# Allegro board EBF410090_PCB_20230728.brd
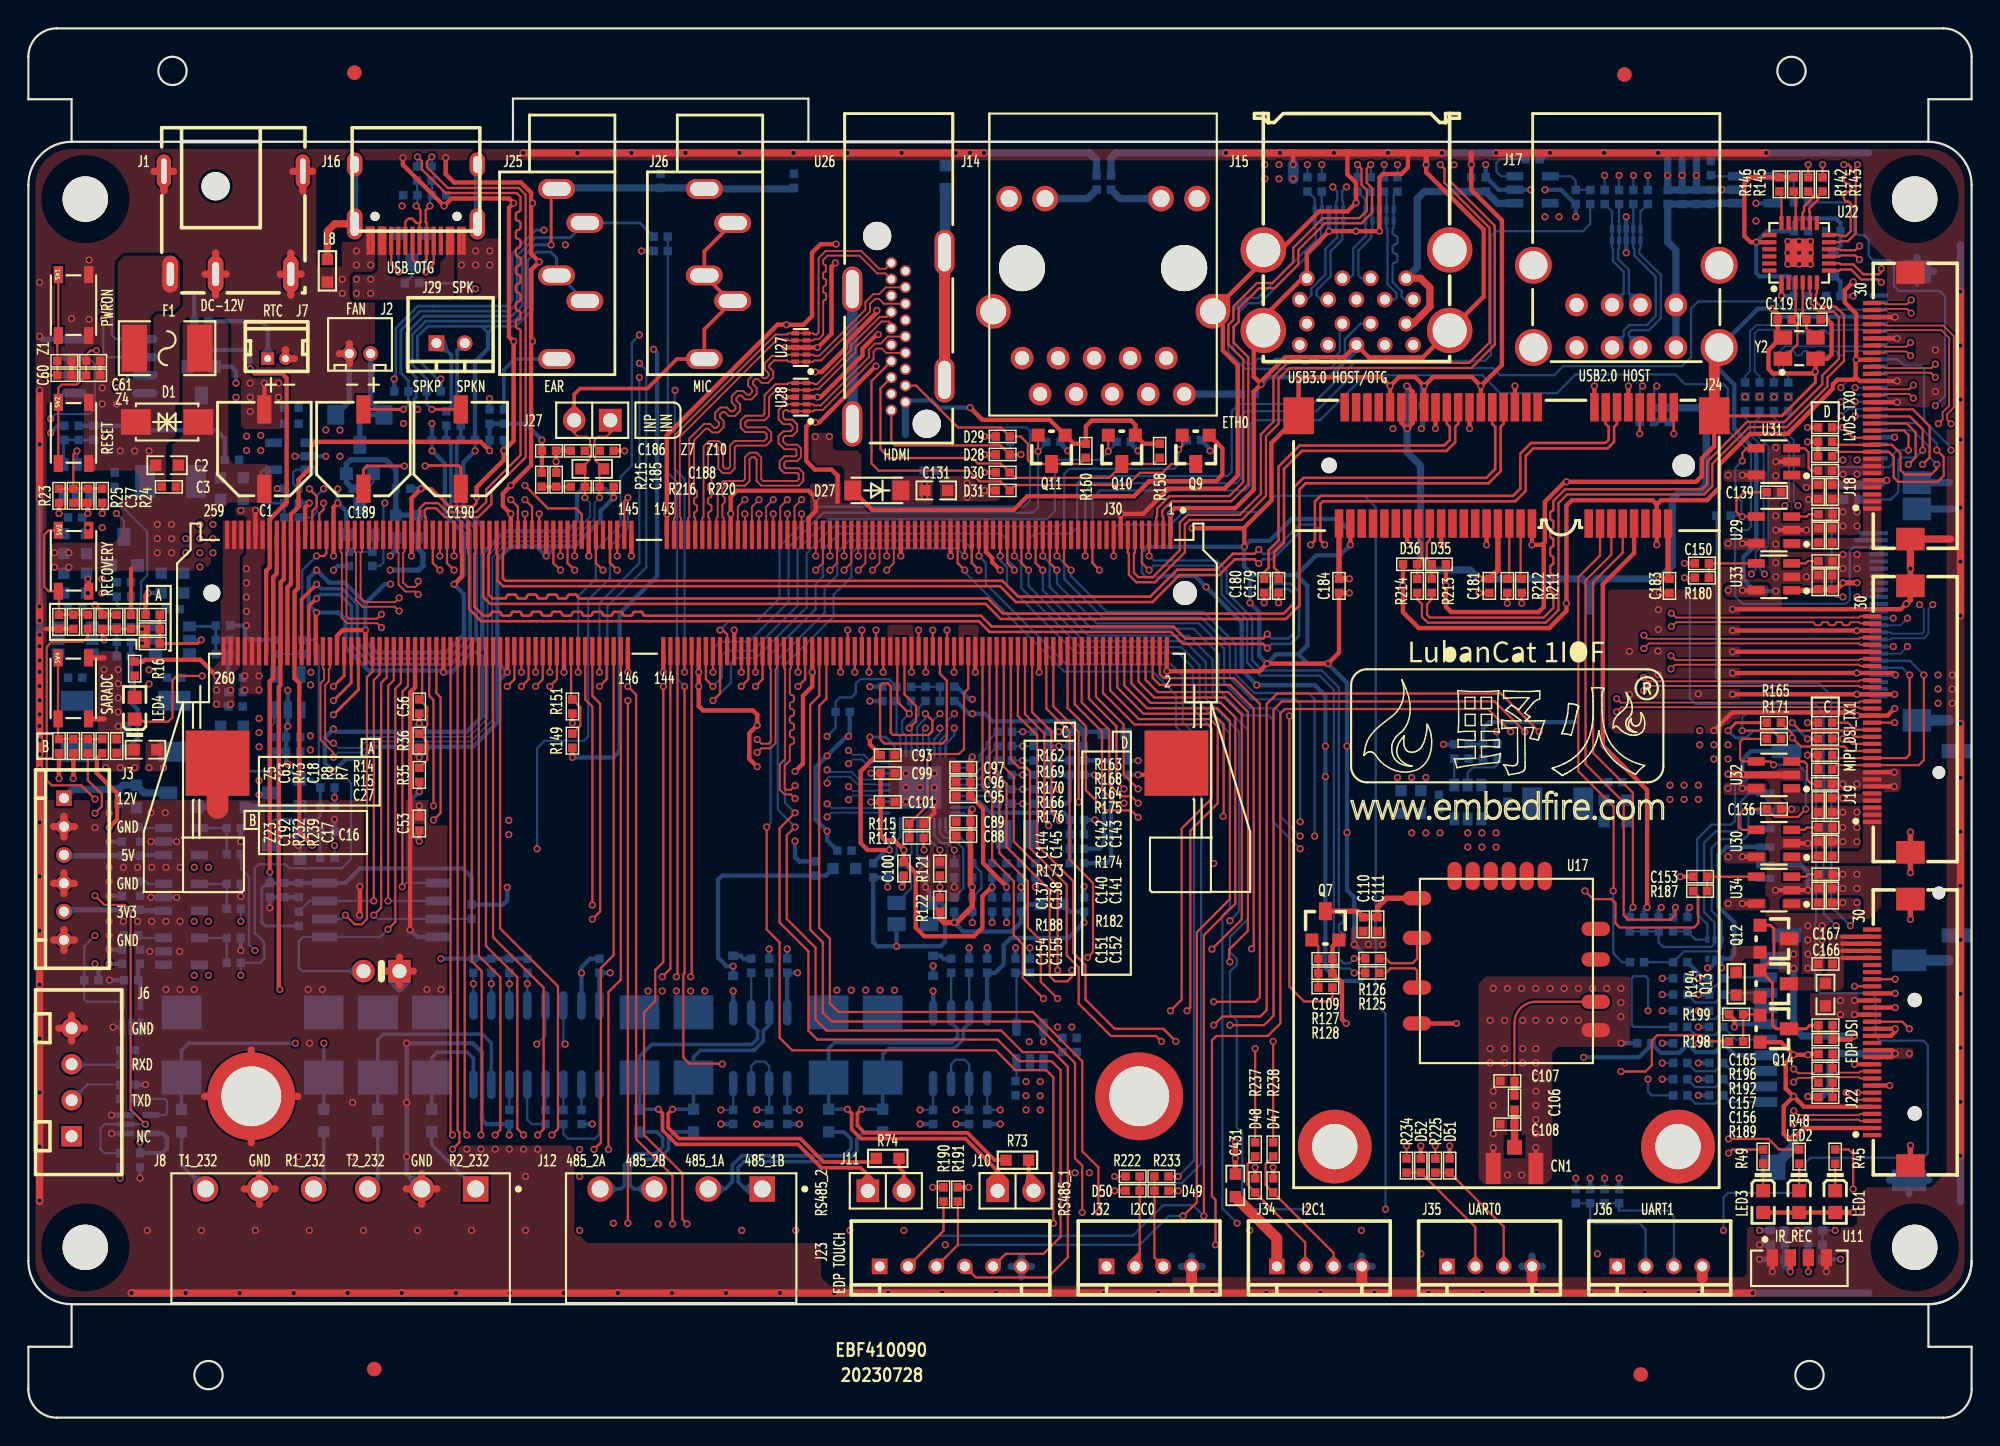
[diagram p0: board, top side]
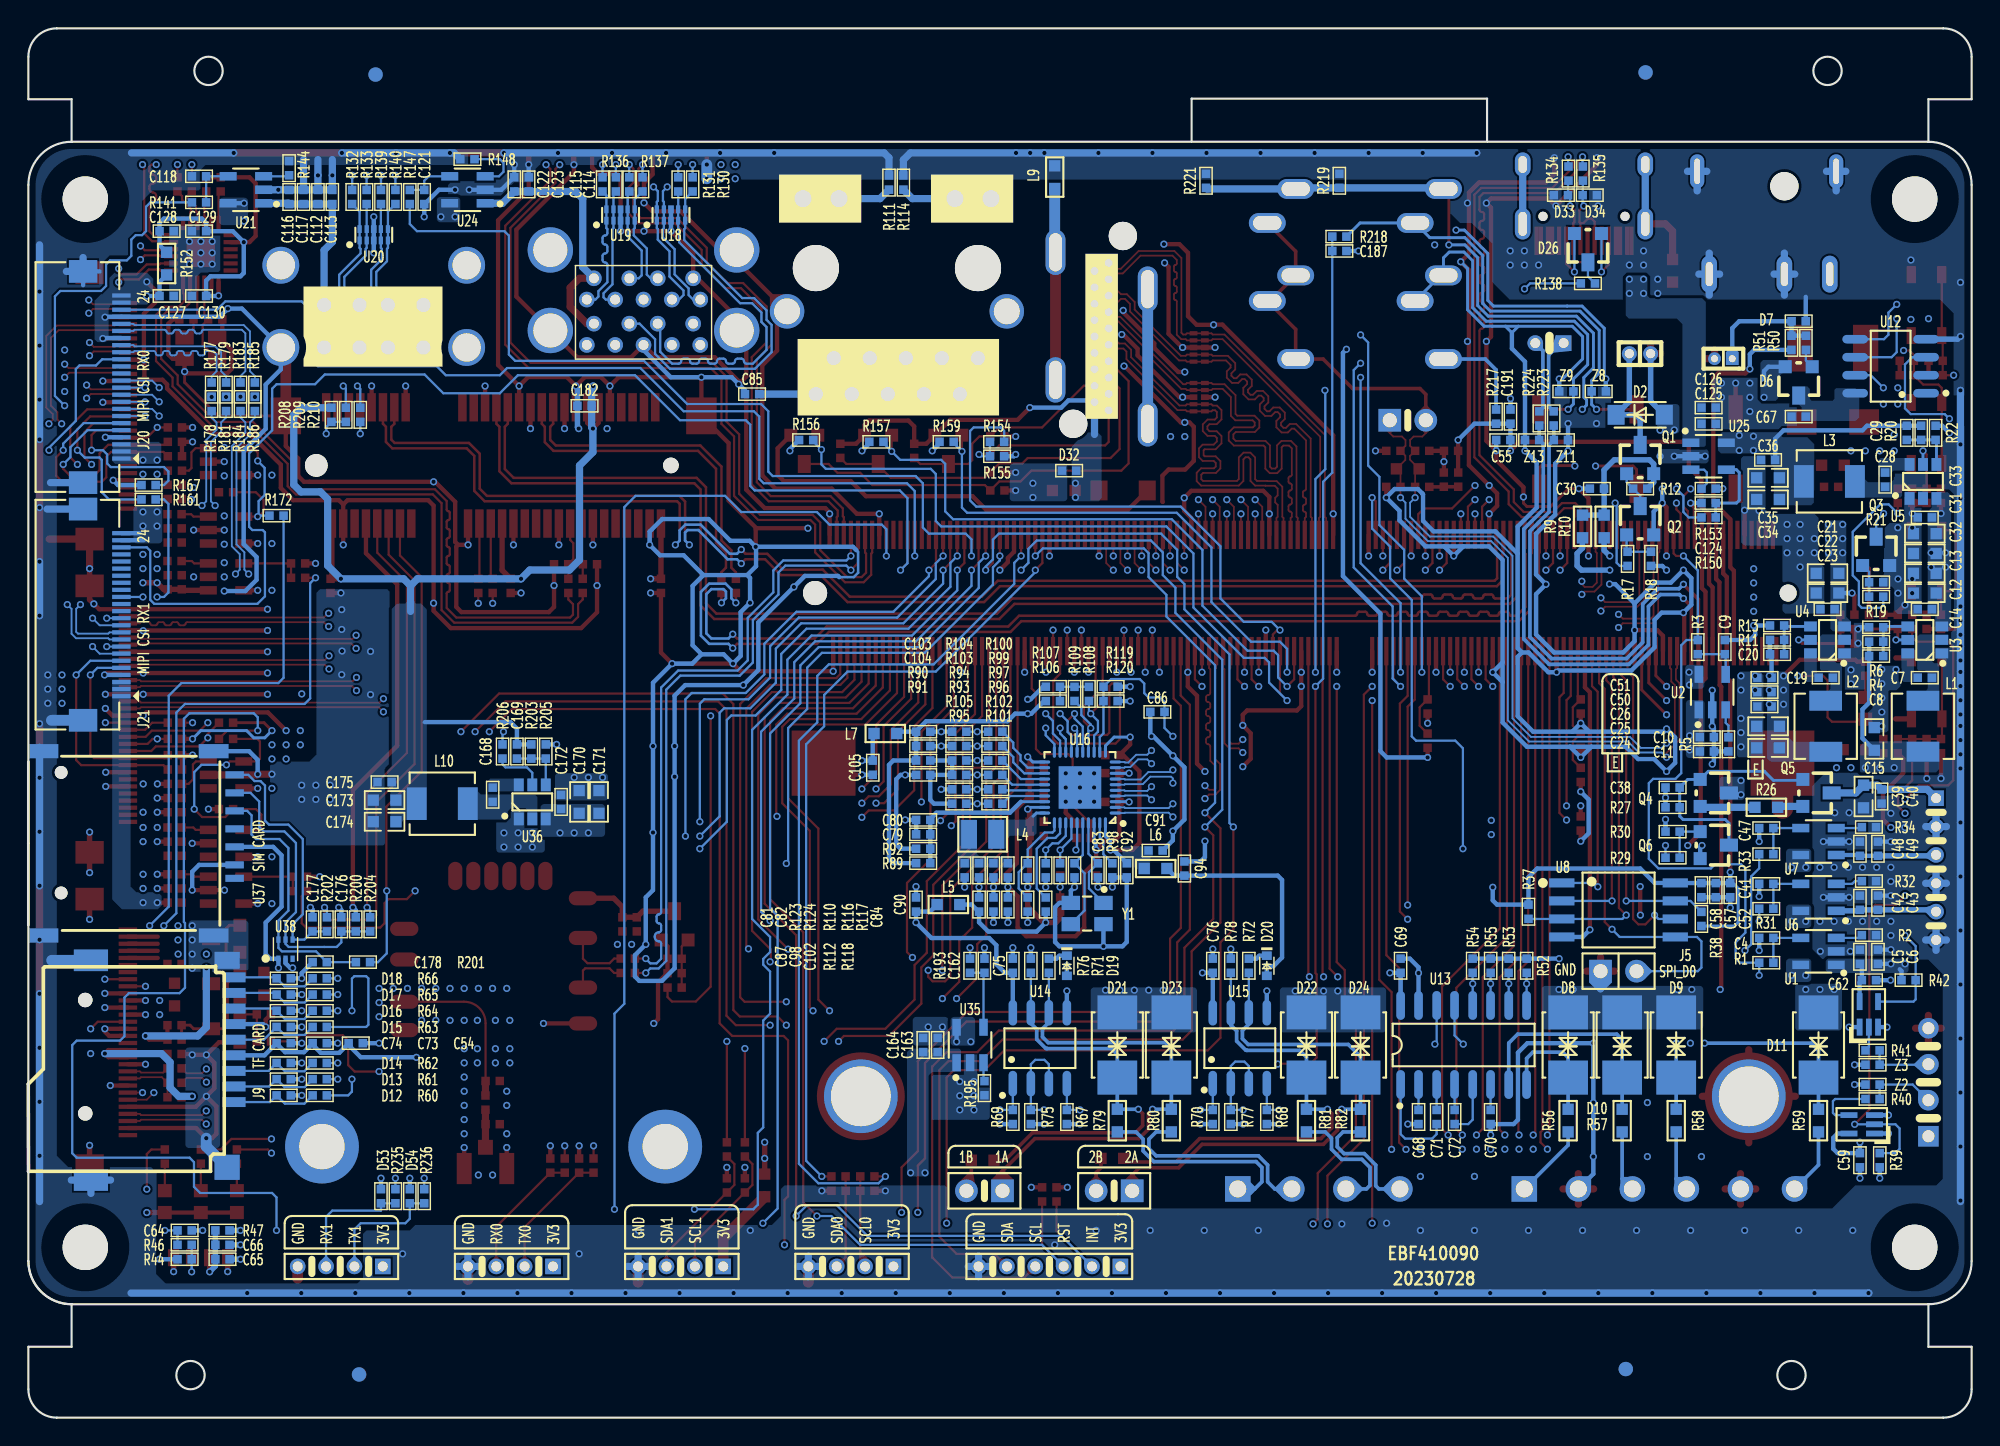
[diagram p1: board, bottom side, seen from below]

Outline 137 x 98 mm; copper layers: TOP, GND02, ART03, ART04, PWR05, BOTTOM. Coordinates in mm from the lower left corner of the outline.
Outline path: circle c10.16,95 r1 ; circle c12.7,3 r1 ; circle c124.3,95 r1 ; circle c125.57,3 r1 ; 0,86.95 arc(0.89,89.11) 3.05,90 ; 0,86.95 arc(0.89,89.11) 3.05,90 ; 0,86.95 0,11.05 ; 0,86.95 0,11.05 ; 3.05,90 3.05,93 0,93 0,96 arc(0.59,97.41) 2,98 135,98 arc(136.41,97.41) 137,96 137,93 133.95,93 133.95,90 ; 3.05,90 133.95,90 ; 3.05,90 133.95,90 ; 0,11.05 arc(0.89,8.89) 3.05,8 ; 0,11.05 arc(0.89,8.89) 3.05,8 ; 133.95,90 arc(136.11,89.11) 137,86.95 ; 133.95,90 arc(136.11,89.11) 137,86.95 ; 3.05,8 3.05,5 0,5 0,2 arc(0.59,0.59) 2,0 135,0 arc(136.41,0.59) 137,2 137,5 133.95,5 133.95,8 ; 3.05,8 133.95,8 ; 3.05,8 133.95,8 ; 133.95,8 arc(136.11,8.89) 137,11.05 ; 133.95,8 arc(136.11,8.89) 137,11.05 ; 133.95,8 arc(136.11,8.89) 137,11.05 ; 34.16,90.04 34.16,93.04 54.99,93.04 54.99,90.04 ; 137,86.95 137,11.05 ; 137,86.95 137,11.05

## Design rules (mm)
net group B_DM1: nets B_DM1 HUB_DM1
net group B_DM2: nets B_DM2 HUB_DM2
net group B_DM3: nets B_DM3 HUB_DM3
net group B_DP1: nets B_DP1 HUB_DP1
net group B_DP2: nets B_DP2 HUB_DP2
net group B_DP3: nets B_DP3 HUB_DP3
net group DIFF_CIE20_REFCLKP: nets PCIE20_REFCLKN PCIE20_REFCLKP
net group DIFF_CIE20_RXP: nets PCIE20_RXN PCIE20_RXP
net group DIFF_ED_AUXP: nets EDP_AUXN EDP_AUXP
net group DIFF_MDI0_PHY: nets MDIN0_PHY MDIP0_PHY
net group DIFF_MDI1_PHY: nets MDIN1_PHY MDIP1_PHY
net group DIFF_MDI2_PHY: nets MDIN2_PHY MDIP2_PHY
net group DIFF_MDI3_PHY: nets MDIN3_PHY MDIP3_PHY
net group DIFF_USB3_HOST1_SSRX: nets USB3_HOST1_SSRXN USB3_HOST1_SSRXP
net group DIFFPAIR7: nets MIC_INN MIC_INP
net group DM4: nets DM4 HUB_DM4
net group DP4: nets DP4 HUB_DP4
net group GMAC1_RXCLK_M1: nets GMAC1_RXCLK_M1 N15599549
net group GMAC1_RXD0_M1: nets GMAC1_RXD0_M1 N15599533
net group GMAC1_RXD1_M1: nets GMAC1_RXD1_M1 N15599537
net group GMAC1_RXD2_M1: nets GMAC1_RXD2_M1 N15599541
net group GMAC1_RXD3_M1: nets GMAC1_RXD3_M1 N15599545
net group GMAC1_RXDV_CRS_M1: nets GMAC1_RXDV_CRS_M1 N15599553
net group HOST1_DM: nets HOST1_DM USB3_HOST1_DM
net group HOST1_DP: nets HOST1_DP USB3_HOST1_DP
net group HP_DET_L: nets HP_DET_L N15830941
net group OTG0_DM: nets OTG0_DM USB_OTG0_DM
net group OTG0_DP: nets OTG0_DP USB_OTG0_DP
net group PCIE20_CLKREQN_M0: nets N16823854 PCIE20_CLKREQN_M0
net group PCIE20_TXN: nets PCIE20_TXN PE_TXN
net group PCIE20_TXP: nets PCIE20_TXP PE_TXP
net group PCIE20_WAKEN_M0: nets N16811933 PCIE20_WAKEN_M0
net group PWM3_IR: nets N17863087 PWM3_IR
net group SDMMC0_CLK: nets N16793151 SDMMC0_CLK
net group SDMMC0_CMD: nets N16793153 SDMMC0_CMD
net group SDMMC0_D0: nets N16793149 SDMMC0_D0
net group SDMMC0_D1: nets N16793157 SDMMC0_D1
net group SDMMC0_D2: nets N16793147 SDMMC0_D2
net group SDMMC0_D3: nets N16793155 SDMMC0_D3
net group SDMMC0_DET_L: nets N16793300 SDMMC0_DET_L
net group SS_TXN: nets SS_TXN USB3_HOST1_SSTXN
net group SS_TXP: nets SS_TXP USB3_HOST1_SSTXP
net group USB2_HOST2_DM: nets N18057325 USB2_HOST2_DM
net group USB2_HOST2_DP: nets N18057335 USB2_HOST2_DP
net group USB2_HOST3_DM: nets N17770942 USB2_HOST3_DM
net group USB2_HOST3_DP: nets N17770939 USB2_HOST3_DP
net group C_EDP_TX: nets EDP_TX_AUXN EDP_TX_AUXP EDP_TX_D1N EDP_TX_D1P
net group C_HDMI: nets HDMI_TX0N_PORT HDMI_TX0P_PORT HDMI_TX1N_PORT HDMI_TX1P_PORT HDMI_TX2N_PORT HDMI_TX2P_PORT HDMI_TXCLKN_PORT HDMI_TXCLKP_PORT
net group C_MIPI_CSI_RX_D0-3: nets MIPI_CSI_RX_CLK0N MIPI_CSI_RX_CLK0P MIPI_CSI_RX_CLK1N MIPI_CSI_RX_CLK1P MIPI_CSI_RX_D0N MIPI_CSI_RX_D0P MIPI_CSI_RX_D1N MIPI_CSI_RX_D1P
net group C_MIPI_DSI_TX0-3: nets MIPI_DSI_TX0_CLKN MIPI_DSI_TX0_CLKP MIPI_DSI_TX0_D0N MIPI_DSI_TX0_D0P MIPI_DSI_TX0_D1N MIPI_DSI_TX0_D1P MIPI_DSI_TX0_D2N MIPI_DSI_TX0_D2P MIPI_DSI_TX0_D3N MIPI_DSI_TX0_D3P
net group C_MIPI_DSI_TX1-D0-3: nets MIPI_DSI_TX1_CLKN MIPI_DSI_TX1_CLKP MIPI_DSI_TX1_D0N MIPI_DSI_TX1_D0P MIPI_DSI_TX1_D1N MIPI_DSI_TX1_D1P MIPI_DSI_TX1_D2N MIPI_DSI_TX1_D2P MIPI_DSI_TX1_D3N MIPI_DSI_TX1_D3P
net group CSI_RX_D2N_S0: nets CSI_RX_D2N_S0 CSI_RX_D2N_S1 MIPI_CSI_RX_D2N
net group CSI_RX_D2P_S0: nets CSI_RX_D2P_S0 CSI_RX_D2P_S1 MIPI_CSI_RX_D2P
net group CSI_RX_D3N_S0: nets CSI_RX_D3N_S0 CSI_RX_D3N_S1 MIPI_CSI_RX_D3N
net group CSI_RX_D3P_S0: nets CSI_RX_D3P_S0 CSI_RX_D3P_S1 MIPI_CSI_RX_D3P
net group PWR: nets 1V05_AVDD_PHY 1V05_DVDD_PHY 1V8_DVDD_PHY 3V3_DVDD_PHY 3V3_OUT 3V3_WLAN 5V_OUT 12V_OUT HUB_3V3 SIM_VDD VCC3V3_SD VCC5V0_USB20_HOST VCC5V0_USB30_HOST VCC_1V8 VCC_RTC VCCA_1V8 VCCIO_ACODEC

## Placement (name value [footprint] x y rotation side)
C1  220uF  [EC6P3]  16.64 68.32 180 top
C2  4.7uF  [C0603]  9.78 67.18 180 top
C3  0.1uF  [C0402]  9.91 65.66 180 top
C4  0.1uF  [C0402]  14.48 33.84 0 bottom
C5  10uF  [C0402]  7.87 32.51 90 bottom
C6  0.1uF  [C0402]  6.6 32.51 90 bottom
C7  0.1uF  [C0402]  3.3 52.2 180 bottom
C8  NC  [C0402]  6.73 53.72 180 bottom
C9  0.1uF  [C0402]  17.4 54.35 90 bottom
C10  10uF  [C0402]  18.67 48 180 bottom
C11  0.1uF  [C0402]  18.67 46.99 180 bottom
C12  10uF  [C0603]  3.3 58.16 0 bottom
C13  10uF  [C0603]  3.3 59.56 0 bottom
C14  0.1uF  [C0402]  3.3 57.02 0 bottom
C15  22uF  [C0603]  6.86 47.88 90 bottom
C16  22uF  [C0603]  8.26 47.12 0 top
C17  0.1uF  [C0402]  6.22 47.37 90 top
C18  NC  [C0402]  5.21 56.13 270 top
C19  0.1uF  [C0402]  10.29 52.2 180 bottom
C20  NC  [C0402]  13.72 53.85 180 bottom
C21  10uF  [C0603]  10.16 59.56 0 bottom
C22  10uF  [C0603]  10.16 58.16 0 bottom
C23  0.1uF  [C0402]  10.16 57.02 0 bottom
C24  22uF  [C0603]  14.35 47.24 0 bottom
C25  22uF  [C0603]  14.35 48.77 0 bottom
C26  0.1uF  [C0402]  14.61 50.16 0 bottom
C27  NC  [C0402]  8.76 54.61 0 top
C28  0.1uF  [C0402]  6.1 66.17 270 bottom
C29  NC  [C0402]  4.57 69.47 270 bottom
C30  0.1uF  [C0402]  26.42 65.53 0 bottom
C31  10uF  [C0603]  3.3 62.36 0 bottom
C32  10uF  [C0603]  3.3 60.96 0 bottom
C33  0.1uF  [C0402]  3.3 63.5 0 bottom
C34  22uF  [C0603]  14.35 64.77 0 bottom
C35  22uF  [C0603]  14.35 66.29 0 bottom
C36  0.1uF  [C0402]  14.35 67.56 0 bottom
C37  NC  [C0402]  4.19 65.02 90 top
C38  0.1uF  [C0402]  21.08 44.45 180 bottom
C39  10uF  [C0603]  7.62 43.81 270 bottom
C40  0.1uF  [C0402]  6.35 43.81 270 bottom
C41  0.1uF  [C0402]  14.48 37.65 0 bottom
C42  10uF  [C0402]  7.87 36.32 90 bottom
C43  0.1uF  [C0402]  6.6 36.32 90 bottom
C47  0.1uF  [C0402]  14.48 41.59 0 bottom
C48  10uF  [C0402]  7.87 40.13 90 bottom
C49  0.1uF  [C0402]  6.6 40.13 90 bottom
C50  0.1uF  [C0402]  14.61 51.18 0 bottom
C51  0.1uF  [C0402]  14.61 52.2 0 bottom
C52  0.1uF  [C0402]  17.02 37.21 270 bottom
C53  0.1uF  [C0402]  27.56 41.91 90 top
C54  0.1uF  [C0402]  113.92 26.41 180 bottom
C55  0.1uF  [C0402]  33.02 68.96 0 bottom
C56  1uF  [C0402]  27.56 50.16 270 top
C57  4.7uF  [C0402]  18.03 37.21 270 bottom
C58  0.1uF  [C0402]  19.05 37.21 270 bottom
C59  0.1uF  [C0402]  7.87 18.16 270 bottom
C60  0.1uF  [C0402]  2.54 73.53 0 top
C61  0.1uF  [C0402]  4.57 74.55 0 top
C62  0.1uF  [C0402]  7.24 30.86 180 bottom
C63  0.1uF  [C0402]  3.17 56.13 270 top
C64  NC  [C0402]  125.98 13.21 180 bottom
C65  0.1uF  [C0402]  123.32 11.17 180 bottom
C66  1uF  [C0402]  123.32 12.19 180 bottom
C67  0.1uF  [C0402]  12.19 70.61 0 bottom
C68  0.1uF  [C0402]  38.99 21.21 270 bottom
C69  4.7uF  [C0402]  40.26 31.88 90 bottom
C70  0.1uF  [C0402]  33.91 21.21 270 bottom
C71  0.1uF  [C0402]  37.72 21.21 270 bottom
C72  0.1uF  [C0402]  36.45 21.21 90 bottom
C73  4.7uF  [C0402]  116.46 26.41 180 bottom
C74  0.1uF  [C0402]  119 26.41 180 bottom
C75  0.1uF  [C0402]  67.59 31.88 90 bottom
C76  0.1uF  [C0402]  53.5 31.88 90 bottom
C79  0.1uF  [C0402]  73.91 41.15 0 bottom
C80  4.7uF  [C0402]  73.91 42.16 0 bottom
C81  0.1uF  [C0402]  70.99 38.61 270 bottom
C82  4.7uF  [C0402]  69.98 38.61 270 bottom
C83  18pF  [C0402]  61.59 38.61 270 bottom
C84  18pF  [C0402]  63.25 38.61 270 bottom
C85  0.1uF  [C0402]  85.98 72.2 0 bottom
C86  0.1uF  [C0402]  57.4 49.78 0 bottom
C87  4.7uF  [C0402]  69.98 36.19 90 bottom
C88  0.1uF  [C0402]  65.91 41.02 180 top
C89  0.1uF  [C0402]  65.91 42.04 180 top
C90  0.1uF  [C0402]  74.42 36.19 90 bottom
C91  4.7uF  [C0402]  57.53 40 180 bottom
C92  0.1uF  [C0402]  59.56 38.61 270 bottom
C93  0.1uF  [C0402]  60.58 46.73 0 top
C94  0.1uF  [C0402]  55.5 38.73 90 bottom
C95  4.7uF  [C0402]  65.91 43.81 180 top
C96  0.1uF  [C0402]  65.91 44.83 180 top
C97  0.1uF  [C0402]  65.91 45.85 180 top
C98  4.7uF  [C0402]  68.96 36.19 270 bottom
C99  0.1uF  [C0402]  60.58 45.46 0 top
C100  0.1uF  [C0402]  61.72 38.73 270 top
C101  0.1uF  [C0402]  60.58 43.43 0 top
C102  4.7uF  [C0402]  67.94 36.19 270 bottom
C103  4.7uF  [C0402]  73.91 48.39 180 bottom
C104  0.1uF  [C0402]  73.91 47.37 180 bottom
C105  0.1uF  [C0402]  77.47 45.85 270 bottom
C106  10pF  [C0402]  104.78 22.22 270 top
C107  NC  [C0402]  104.27 23.75 180 top
C108  NC  [C0402]  104.27 20.7 180 top
C109  0.1uF  [C0402]  91.44 32.37 180 top
C110  10uF  [C0402]  94.11 34.8 270 top
C111  0.1uF  [C0402]  95.12 34.8 270 top
C112  1uF  [C0402]  116.59 86.1 90 bottom
C113  1uF  [C0402]  115.57 86.1 90 bottom
C114  0.1uF  [C0402]  95.58 86.99 90 bottom
C115  0.1uF  [C0402]  96.52 86.99 90 bottom
C116  10uF  [C0402]  118.62 86.1 90 bottom
C117  0.1uF  [C0402]  117.6 86.1 90 bottom
C118  0.1uF  [C0402]  124.97 87.56 0 bottom
C119  NC  [C0402]  123.83 77.47 180 top
C120  NC  [C0402]  125.86 77.47 180 top
C121  0.1uF  [C0402]  109.09 86.1 270 bottom
C122  10uF  [C0402]  102.74 86.99 90 bottom
C123  0.1uF  [C0402]  101.73 86.99 90 bottom
C124  0.1uF  [C0402]  18.54 64.51 0 bottom
C125  10uF  [C0402]  18.54 70.1 180 bottom
C126  0.1uF  [C0402]  18.54 71.25 180 bottom
C127  0.1uF  [C0402]  127.25 79.12 180 bottom
C128  4.7uF  [C0402]  127.25 83.69 180 bottom
C129  0.1uF  [C0402]  124.97 83.69 0 bottom
C130  0.1uF  [C0402]  124.97 79.12 0 bottom
C131  1uF  [C0603]  64.01 65.4 0 top
C136  0.1uF  [C0402]  123.06 42.92 0 top
C137  10uF  [C0402]  126.19 40.13 90 top
C138  0.1uF  [C0402]  127.18 40.13 90 top
C139  0.1uF  [C0402]  123.06 65.28 0 top
C140  10uF  [C0402]  126.19 62.23 90 top
C141  0.1uF  [C0402]  127.18 62.23 90 top
C142  10uF  [C0402]  126.19 65.3 270 top
C143  0.1uF  [C0402]  127.18 65.3 270 top
C144  10uF  [C0402]  126.19 43.2 270 top
C145  0.1uF  [C0402]  127.18 43.2 270 top
C150  0.1uF  [C0402]  117.98 60.26 180 top
C151  10uF  [C0402]  126.19 58.93 90 top
C152  0.1uF  [C0402]  127.18 58.93 90 top
C153  0.1uF  [C0402]  117.86 38.16 180 top
C154  10uF  [C0402]  126.19 36.83 90 top
C155  0.1uF  [C0402]  127.18 36.83 90 top
C156  0.1uF  [C0402]  126.7 23.62 0 top
C157  0.1uF  [C0402]  126.7 24.64 0 top
C162  0.1uF  [C0402]  69.6 31.88 90 bottom
C163  10uF  [C0402]  72.9 26.29 90 bottom
C164  0.1uF  [C0402]  73.91 26.29 90 bottom
C165  0.1uF  [C0402]  126.7 27.68 180 top
C166  10uF  [C0603]  126.7 29.84 270 top
C167  0.1uF  [C0402]  126.7 32 180 top
C168  0.1uF  [C0402]  104.27 43.94 270 bottom
C169  NC  [C0402]  102.56 46.99 270 bottom
C170  10uF  [C0603]  98.17 43.43 90 bottom
C171  10uF  [C0603]  96.77 43.43 90 bottom
C172  0.1uF  [C0402]  99.44 43.43 90 bottom
C173  22uF  [C0603]  111.89 43.56 0 bottom
C174  22uF  [C0603]  111.89 42.04 0 bottom
C175  0.1uF  [C0402]  111.89 44.83 0 bottom
C176  33pF  [C0402]  114.94 34.8 90 bottom
C177  33pF  [C0402]  116.97 34.8 90 bottom
C178  33pF  [C0402]  116.46 32.13 0 bottom
C179  0.1uF  [C0402]  88.14 58.67 90 top
C180  0.1uF  [C0402]  87.12 58.67 90 top
C181  0.1uF  [C0402]  103 58.67 270 top
C182  0.1uF  [C0402]  97.79 71.37 0 bottom
C183  4.7uF  [C0402]  115.7 58.67 270 top
C184  4.7uF  [C0402]  92.4 58.67 270 top
C185  1uF  [C0402]  37.21 66.17 90 top
C186  0.1uF  [C0402]  36.7 68.2 0 top
C187  1uF  [C0402]  44.58 82.29 180 bottom
C188  100pF  [C0603]  39.75 66.93 0 top
C189  220uF  [EC6P3]  23.62 68.32 180 top
C190  220uF  [EC6P3]  30.48 68.32 180 top
C191  0.1uF  [C0402]  32.51 70.61 90 bottom
C192  0.1uF  [C0402]  3.17 47.37 270 top
C431  10uF  [C0603]  85.09 16.38 90 top
CN1  WiFi-Ant  [UFL-3]  104.78 17.57 180 top
D1  SMAJ13CA  [SMA214-CA]  9.78 70.23 0 top
D2  1N4148W  [SOD-123]  23.37 70.74 0 bottom
D6  BAT54C  [SOT23]  12.19 73.14 0 bottom
D7  KLXES15AAA1  [ES0402]  12.19 77.34 0 bottom
D8  SMBJ15CA  [SMB-CA]  28.45 26.29 270 bottom
D9  SMBJ15CA  [SMB-CA]  20.83 26.29 270 bottom
D10  SMBJ15CA  [SMB-CA]  24.64 26.29 270 bottom
D11  SMBJ15CA  [SMB-CA]  10.79 26.29 270 bottom
D12  KLXES15AAA1  [ES0402]  119 22.73 0 bottom
D13  KLXES15AAA1  [ES0402]  119 23.87 0 bottom
D14  KLXES15AAA1  [ES0402]  119 25.02 0 bottom
D15  KLXES15AAA1  [ES0402]  119 27.56 0 bottom
D16  KLXES15AAA1  [ES0402]  119 28.7 0 bottom
D17  KLXES15AAA1  [ES0402]  119 29.84 0 bottom
D18  KLXES15AAA1  [ES0402]  119 30.99 0 bottom
D19  RB521S-30  [SOD523]  63.78 31.88 270 bottom
D20  RB521S-30  [SOD523]  49.69 31.88 270 bottom
D21  SMBJ6.5CA  [SMB-CA]  60.23 26.29 270 bottom
D22  SMBJ6.5CA  [SMB-CA]  46.89 26.29 270 bottom
D23  SMBJ6.5CA  [SMB-CA]  56.42 26.29 270 bottom
D24  SMBJ6.5CA  [SMB-CA]  43.08 26.29 270 bottom
D26  BAT54A  [SOT23]  27.05 82.54 0 bottom
D27  1N5819W  [SOD-123]  59.82 65.4 0 top
D28  KLXES15AAA1  [ES0402]  68.69 67.94 0 top
D29  KLXES15AAA1  [ES0402]  68.69 69.21 0 top
D30  KLXES15AAA1  [ES0402]  68.69 66.67 0 top
D31  KLXES15AAA1  [ES0402]  68.69 65.4 0 top
D32  KLXES15AAA1  [ES0402]  63.63 66.8 180 bottom
D33  KLXES15AAA1  [ES0402]  28.96 86.23 180 bottom
D34  KLXES15AAA1  [ES0402]  26.92 86.23 0 bottom
D35  KLXES15AAA1  [ES0402]  99.44 60.2 180 top
D36  KLXES15AAA1  [ES0402]  97.41 60.2 0 top
D47  KLXES15AAA1  [ES0402]  87.76 16.38 270 top
D48  KLXES15AAA1  [ES0402]  86.49 16.38 270 top
D49  KLXES15AAA1  [ES0402]  79.88 16 180 top
D50  KLXES15AAA1  [ES0402]  77.85 16 0 top
D51  KLXES15AAA1  [ES0402]  100.2 17.78 270 top
D52  KLXES15AAA1  [ES0402]  98.17 17.78 270 top
D53  KLXES15AAA1  [ES0402]  112.14 15.62 270 bottom
D54  KLXES15AAA1  [ES0402]  110.11 15.62 270 bottom
F1  SMD1812P200TF16  [F1812]  9.78 75.44 0 top
H1  -  [NPTH_M3]  4.01 85.96 0 top
H2  -  [NPTH_M3]  132.99 85.96 0 top
H3  -  [NPTH_M3]  4.01 12.01 0 top
H4  -  [NPTH_M3]  132.99 12.01 0 top
J1  DC-044A-20A  [DC_IN_TH_3P_10R1X11R6]  14.45 85.16 270 top
J2  A1501WV-2P  [ZH1P5MM_TH_2P]  23.38 75.05 180 top
J3  PH-6A  [PH-1X6-2P0]  2.51 38.69 270 top
J5  NC  [HDR1X2-2R54-TM-VM]  24.89 31.49 180 bottom
J6  XH-4A  [XH2P54-4P]  3.05 23.66 90 top
J7  1.25T-2A  [GH1P25_TH_2P]  17.5 74.7 0 top
J8  CON6  [DB2ERC-3P81-6P]  22.01 16.13 180 top
J9  TF_Card  [TFCARD]  132.99 25.46 270 bottom
J10  -  [HDR1X2-2R54-TM-VM]  69.6 16 0 top
J11  -  [HDR1X2-2R54-TM-VM]  60.45 16 0 top
J12  WJ15EDGRC-3.81-4P  [DB2ERC-3P81-4P]  46.02 16.13 180 top
J14  -  [HY911130A]  75.77 81.09 0 top
J15  USB3D0_USB2D0-A-D  [USB3D0-AF-18P]  93.63 78.87 180 top
J16  TYPE-C  [TYPE-C-31-M-12]  27.33 83.3 180 top
J17  -  [USB-A-D]  112.65 81.99 0 top
J18  FPC_0R5_30P_D  [FPC-30P-0P5]  131.33 71.37 90 top
J19  FPC_0R5_30P_D  [FPC-30P-0P5]  131.33 49.27 90 top
J20  FPC_0P5_24P_D  [FPC_24P_0P5]  131.79 73.4 90 bottom
J21  FPC_0P5_24P_D  [FPC_24P_0P5]  131.79 56.64 90 bottom
J22  FPC_0R5_30P_D  [FPC-30P-0P5]  131.33 27.18 90 top
J23  PH-6A  [PH-1X6-2P0]  65.01 10.67 0 top
J24  MINI-PCIE  [PCIE_52P]  104.2 67.17 180 top
J25  PJ-325C5-G  [EAR_JACK]  38.14 80.57 270 top
J26  PJ-325C5-R  [EAR_JACK]  48.55 80.57 270 top
J27  -  [HDR1X2-2R54-TM-VM]  39.75 70.36 180 top
J29  PH  [PH-1X2-2P0_L]  29.76 75.8 0 top
J30  -  [AS0A826-H2SB-7H]  47.24 58.17 180 top
J32  PH-4A  [PH-1X4-2P0]  79.01 10.67 0 top
J34  PH-4A  [PH-1X4-2P0]  91.01 10.67 0 top
J35  PH-4A  [PH-1X4-2P0]  103.01 10.67 0 top
J36  PH-4A  [PH-1X4-2P0]  115.01 10.67 0 top
L1  3.3uH  [L4520]  3.43 48.77 270 bottom
L2  3.3uH  [L4520]  10.29 48.77 270 bottom
L3  3.3uH  [L4520]  10.03 66.04 0 bottom
L4  2.2uH  [L2520]  69.72 41.15 0 bottom
L5  100R 100MHz  [L0603]  72.14 36.19 0 bottom
L6  100R 100MHz  [L0603]  57.53 38.73 180 bottom
L7  100R 100MHz  [L0603]  76.58 48.26 0 bottom
L8  120R 100MHz  [L0603]  21.08 80.9 270 top
L9  330R 100MHz  [L0603]  64.64 87.5 90 bottom
L10  3.3uH  [L4520]  107.82 43.31 0 bottom
LED1  BLUE  [LED0603]  127.38 15.24 90 top
LED2  BLUE  [LED0603]  124.84 15.24 90 top
LED3  BLUE  [LED0603]  122.3 15.24 90 top
LED4  RED  [LED0603]  7.49 50.04 270 top
NOREF  -  []  3.05 8 90 top
NOREF#2  -  [unnamed#2]  113.67 3.05 0 top
NOREF#3  -  []  50.85 0 90 top
NOREF#4  -  [unnamed#2]  112.52 94.74 0 top
NOREF#5  -  [unnamed#2]  24.38 3.43 0 top
NOREF#6  -  []  104.31 54.17 0 top
NOREF#7  -  []  0 86.95 0 top
NOREF#8  -  [unnamed#2]  22.99 94.87 0 top
NOREF#9  -  [unnamed#2]  112.52 94.74 180 bottom
NOREF#10  -  [unnamed#2]  113.69 3.05 180 bottom
NOREF#11  -  [unnamed#2]  24.38 3.43 180 bottom
NOREF#12  -  [unnamed#2]  22.99 94.89 180 bottom
Q1  AO3407  [SOT23]  23.37 67.58 180 bottom
Q2  SS8050  [SOT23]  23.37 63.26 180 bottom
Q3  SS8050  [SOT23]  6.73 61.1 180 bottom
Q4  AO3407  [SOT23]  18.15 44.07 270 bottom
Q5  AO3407  [SOT23]  10.91 44.07 270 bottom
Q6  SS8050  [SOT23]  18.15 40.38 270 bottom
Q7  AO3407  [SOT23]  91.44 34.68 0 top
Q9  2SK3018  [SOT23]  82.3 68.31 180 top
Q10  2SK3018  [SOT23]  77.09 68.31 180 top
Q11  2SK3018  [SOT23]  72.14 68.31 180 top
Q12  AO3407  [SOT23]  123.08 33.78 270 top
Q13  AO3407  [SOT23]  123.08 30.61 270 top
Q14  SS8050  [SOT23]  123.08 27.43 270 top
R1  1K  [R0402]  14.48 32.09 180 bottom
R2  3.4K  [R0402]  7.24 34.03 180 bottom
R3  1K  [R0402]  19.3 54.35 270 bottom
R4  100K  [R0402]  6.73 54.74 180 bottom
R5  6.8K  [R0402]  17.14 47.5 270 bottom
R6  30K  [R0402]  6.73 55.75 0 bottom
R7  140K  [R0402]  7.24 56.13 270 top
R8  20K  [R0402]  6.22 56.13 90 top
R9  NC  [R0603]  27.43 62.86 90 bottom
R10  0R  [R0603]  25.91 62.86 90 bottom
R11  115K  [R0402]  13.72 54.86 180 bottom
R12  20K  [R0402]  23.37 65.53 0 bottom
R13  20K  [R0402]  13.72 55.88 0 bottom
R14  140K  [R0402]  8.76 56.64 0 top
R15  20K  [R0402]  8.76 55.62 180 top
R16  4.7K  [R0402]  7.49 52.83 270 top
R17  1K  [R0402]  24.26 60.58 90 bottom
R18  10K  [R0402]  22.61 60.58 270 bottom
R19  1K  [R0402]  6.73 57.91 0 bottom
R20  115K  [R0402]  3.56 69.47 270 bottom
R21  10K  [R0402]  6.73 58.93 180 bottom
R22  20K  [R0402]  2.54 69.47 90 bottom
R23  NC  [R0402]  2.16 65.02 90 top
R24  1K  [R0402]  5.21 65.02 90 top
R25  NC  [R0402]  3.17 65.02 270 top
R26  0R  [R0603]  14.48 43.05 180 bottom
R27  20K  [R0402]  21.08 43.05 180 bottom
R29  510R  [R0402]  21.08 39.5 180 bottom
R30  10K  [R0402]  21.08 41.34 0 bottom
R31  1K  [R0402]  14.48 35.9 180 bottom
R32  6.8K  [R0402]  7.24 37.84 180 bottom
R33  1K  [R0402]  14.48 39.75 180 bottom
R34  6.8K  [R0402]  7.24 41.65 180 bottom
R35  25.5K  [R0402]  27.56 45.34 90 top
R36  10K  [R0402]  27.56 47.75 270 top
R37  10K  [R0402]  31.24 35.69 270 bottom
R38  10K  [R0402]  19.05 35.18 90 bottom
R39  10K  [R0402]  6.48 18.16 90 bottom
R40  560R  [R0402]  6.99 22.48 0 bottom
R41  560R  [R0402]  6.99 25.91 0 bottom
R42  10K  [R0402]  4.45 30.86 180 bottom
R43  100R  [R0402]  4.19 56.13 270 top
R44  10K  [R0402]  125.98 11.17 180 bottom
R45  470R  [R0402]  127.38 18.41 90 top
R46  22R  [R0402]  125.98 12.19 180 bottom
R47  22R  [R0402]  123.32 13.21 180 bottom
R48  470R  [R0402]  124.84 18.41 90 top
R49  470R  [R0402]  122.3 18.41 90 top
R50  0R  [R0402]  11.68 75.82 90 bottom
R51  NC  [R0402]  12.7 75.82 270 bottom
R52  10K  [R0402]  31.37 31.88 270 bottom
R53  10K  [R0402]  32.64 31.88 270 bottom
R54  10K  [R0402]  35.18 31.88 270 bottom
R55  10K  [R0402]  33.91 31.88 270 bottom
R56  0R  [R0603]  28.45 20.95 270 bottom
R57  0R  [R0603]  24.64 20.95 270 bottom
R58  0R  [R0603]  20.83 20.95 270 bottom
R59  0R  [R0603]  10.79 20.95 270 bottom
R60  22R  [R0402]  116.46 22.73 0 bottom
R61  22R  [R0402]  116.46 23.87 0 bottom
R62  22R  [R0402]  116.46 25.02 0 bottom
R63  22R  [R0402]  116.46 27.56 0 bottom
R64  22R  [R0402]  116.46 28.7 0 bottom
R65  22R  [R0402]  116.46 29.84 0 bottom
R66  0R  [R0402]  116.46 30.99 0 bottom
R67  10K  [R0402]  63.78 21.21 90 bottom
R68  10K  [R0402]  49.69 21.21 90 bottom
R69  10K  [R0402]  67.59 21.21 90 bottom
R70  10K  [R0402]  53.5 21.21 90 bottom
R71  4.7K  [R0402]  65.05 31.88 270 bottom
R72  4.7K  [R0402]  50.96 31.88 270 bottom
R73  120R  [R0603]  69.72 18.16 0 top
R74  120R  [R0603]  60.58 18.29 0 top
R75  10K  [R0402]  66.32 21.21 270 bottom
R76  4.7K  [R0402]  66.32 31.88 90 bottom
R77  10K  [R0402]  52.23 21.21 270 bottom
R78  4.7K  [R0402]  52.23 31.88 90 bottom
R79  0R  [R0603]  60.23 20.95 270 bottom
R80  0R  [R0603]  56.42 20.95 270 bottom
R81  0R  [R0603]  46.89 20.95 270 bottom
R82  0R  [R0603]  43.08 20.95 270 bottom
R89  NC  [R0402]  73.91 39.11 0 bottom
R90  NC  [R0402]  73.91 46.35 180 bottom
R91  0R  [R0402]  73.91 45.34 0 bottom
R92  0R  [R0402]  73.91 40.13 0 bottom
R93  4.7K  [R0402]  71.37 45.34 180 bottom
R94  4.7K  [R0402]  71.37 46.35 180 bottom
R95  4.7K  [R0402]  71.37 43.31 180 bottom
R96  22R  [R0402]  68.83 45.34 180 bottom
R97  22R  [R0402]  68.83 46.35 180 bottom
R98  2.49K  [R0402]  60.58 38.61 270 bottom
R99  22R  [R0402]  68.83 47.37 180 bottom
R100  22R  [R0402]  68.83 48.39 180 bottom
R101  22R  [R0402]  68.83 43.31 180 bottom
R102  22R  [R0402]  68.83 44.32 180 bottom
R103  4.7K  [R0402]  71.37 47.37 0 bottom
R104  4.7K  [R0402]  71.37 48.39 0 bottom
R105  4.7K  [R0402]  71.37 44.32 0 bottom
R106  NC  [R0402]  64.77 50.54 180 bottom
R107  0R  [R0402]  64.77 51.56 0 bottom
R108  4.7K  [R0402]  62.23 51.05 270 bottom
R109  4.7K  [R0402]  63.25 51.05 270 bottom
R110  4.7K  [R0402]  66.55 38.61 90 bottom
R111  510R  [R0402]  76.33 87.12 90 bottom
R112  NC  [R0402]  66.55 36.19 90 bottom
R113  0R  [R0402]  62.61 40.89 0 top
R114  510R  [R0402]  75.31 87.12 90 bottom
R115  NC  [R0402]  62.61 41.91 0 top
R116  4.7K  [R0402]  65.28 38.61 270 bottom
R117  4.7K  [R0402]  64.26 38.61 270 bottom
R118  4.7K  [R0402]  65.28 36.19 270 bottom
R119  NC  [R0402]  60.71 51.56 0 bottom
R120  10K  [R0402]  60.71 50.54 0 bottom
R121  0R  [R0402]  64.26 38.73 270 top
R122  NC  [R0402]  64.26 36.19 270 top
R123  0R  [R0402]  68.96 38.61 90 bottom
R124  0R  [R0402]  67.94 38.61 270 bottom
R125  2.2R  [R0402]  94.74 31.37 0 top
R126  2.2R  [R0402]  94.74 32.38 0 top
R127  10K  [R0402]  91.44 31.35 180 top
R128  510R  [R0402]  91.44 30.34 180 top
R130  2.2R  [R0402]  90.17 86.99 90 bottom
R131  2.2R  [R0402]  91.19 86.99 90 bottom
R132  2.2R  [R0402]  114.17 86.1 90 bottom
R133  2.2R  [R0402]  113.16 86.1 90 bottom
R134  2.2R  [R0402]  28.42 87.76 90 bottom
R135  2.2R  [R0402]  27.41 87.76 90 bottom
R136  2.2R  [R0402]  94.64 86.99 90 bottom
R137  2.2R  [R0402]  93.7 86.99 90 bottom
R138  100R  [R0402]  27.05 80.01 0 bottom
R139  2.2R  [R0402]  112.14 86.1 90 bottom
R140  2.2R  [R0402]  111.12 86.1 90 bottom
R141  1K  [R0402]  124.97 85.72 180 bottom
R142  2.2R  [R0402]  125.48 86.99 90 top
R143  2.2R  [R0402]  126.49 86.99 90 top
R144  3.4K  [R0402]  118.62 88.14 90 bottom
R145  100K  [R0402]  124.46 86.99 270 top
R146  100K  [R0402]  123.44 86.99 270 top
R147  1K  [R0402]  110.11 86.1 90 bottom
R148  3.4K  [R0402]  106.05 88.77 0 bottom
R149  10K  [R0402]  38.35 47.75 90 top
R150  1K  [R0402]  18.54 63.5 180 bottom
R151  15K  [R0402]  38.35 50.16 270 top
R152  0R  [R0603]  127.25 81.41 90 bottom
R153  6.8K  [R0402]  18.54 65.53 180 bottom
R154  1K  [R0402]  68.71 68.83 0 bottom
R155  100K  [R0402]  68.71 67.82 180 bottom
R156  27K  [R0402]  82.17 68.96 180 bottom
R157  10K  [R0402]  77.22 68.83 180 bottom
R158  2.2K  [R0402]  79.76 68.2 270 top
R159  10K  [R0402]  72.26 68.83 180 bottom
R160  2.2K  [R0402]  74.55 68.2 270 top
R161  0R  [R0402]  128.52 64.77 0 bottom
R162  0R  [R0402]  126.67 49.02 0 top
R163  10K  [R0402]  126.67 69.85 0 top
R164  10K  [R0402]  126.67 67.82 0 top
R165  10K  [R0402]  123.06 49.02 0 top
R166  10K  [R0402]  126.67 45.72 0 top
R167  10K  [R0402]  128.52 65.78 180 bottom
R168  10K  [R0402]  126.67 68.83 0 top
R169  10K  [R0402]  126.67 47.88 0 top
R170  10K  [R0402]  126.67 46.73 0 top
R171  1K  [R0402]  123.06 47.88 180 top
R172  1K  [R0402]  119.51 63.63 0 bottom
R173  6.8K  [R0402]  126.7 41.63 0 top
R174  6.8K  [R0402]  126.7 63.73 0 top
R175  6.8K  [R0402]  126.67 66.8 0 top
R176  6.8K  [R0402]  126.67 44.7 0 top
R177  NC  [R0402]  124.08 72.52 90 bottom
R178  0R  [R0402]  124.08 71.5 270 bottom
R179  NC  [R0402]  123.06 72.52 90 bottom
R180  1K  [R0402]  117.98 59.24 0 top
R181  0R  [R0402]  123.06 71.5 270 bottom
R182  6.8K  [R0402]  126.7 60.43 0 top
R183  NC  [R0402]  122.05 72.52 90 bottom
R184  0R  [R0402]  122.05 71.5 270 bottom
R185  NC  [R0402]  121.03 72.52 90 bottom
R186  0R  [R0402]  121.03 71.5 270 bottom
R187  1K  [R0402]  117.86 37.14 0 top
R188  6.8K  [R0402]  126.7 38.33 0 top
R189  NC  [R0402]  126.7 22.6 0 top
R190  10K  [R0402]  64.52 15.75 270 top
R191  10K  [R0402]  65.53 15.75 270 top
R192  NC  [R0402]  126.7 25.65 0 top
R193  1K  [R0402]  70.61 31.88 270 bottom
R194  0R  [R0603]  120.4 30.61 270 top
R195  6.8K  [R0402]  69.6 23.24 270 bottom
R196  20K  [R0402]  126.7 26.67 180 top
R198  1K  [R0402]  120.4 26.54 0 top
R199  10K  [R0402]  120.4 28.45 180 top
R200  15K  [R0402]  113.92 34.8 270 bottom
R201  0R  [R0402]  113.41 32.13 0 bottom
R202  0R  [R0402]  115.95 34.8 270 bottom
R203  100K  [R0402]  101.54 46.99 270 bottom
R204  0R  [R0402]  112.9 34.8 270 bottom
R205  30K  [R0402]  100.52 46.99 90 bottom
R206  1K  [R0402]  103.57 46.99 270 bottom
R208  4.7K  [R0402]  115.63 70.74 270 bottom
R209  22R  [R0402]  114.62 70.74 270 bottom
R210  22R  [R0402]  113.6 70.74 270 bottom
R211  100R  [R0402]  105.28 58.67 270 top
R212  100R  [R0402]  104.27 58.67 270 top
R213  2.2R  [R0402]  98.93 58.67 270 top
R214  2.2R  [R0402]  97.92 58.67 270 top
R215  120R  [R0402]  36.2 66.17 270 top
R216  2.2K  [R0402]  38.73 65.66 0 top
R217  10K  [R0402]  33.53 70.61 90 bottom
R218  22R  [R0402]  44.58 83.31 180 bottom
R219  0R  [R0402]  44.58 87.25 90 bottom
R220  2.2K  [R0402]  40.77 65.66 0 top
R221  0R  [R0402]  53.98 87.25 90 bottom
R222  510R  [R0402]  77.85 17.02 180 top
R223  0R  [R0402]  29.46 70.48 90 bottom
R224  0R  [R0402]  30.48 70.48 90 bottom
R225  510R  [R0402]  99.19 17.78 90 top
R232  100R  [R0402]  4.19 47.37 270 top
R233  510R  [R0402]  79.88 17.02 0 top
R234  510R  [R0402]  97.16 17.78 90 top
R235  510R  [R0402]  111.12 15.62 90 bottom
R236  510R  [R0402]  109.09 15.62 90 bottom
R237  510R  [R0402]  86.49 18.92 90 top
R238  510R  [R0402]  87.76 18.92 90 top
R239  10K  [R0402]  5.21 47.37 270 top
SS1  M2X3mm  [T3R2-5R2_TOPSMT]  116.3 19.12 180 bottom
SS2  M2X3mm  [T3R2-5R2_TOPSMT]  92.1 19.12 180 bottom
SS5  M2.5X3mm  [SMTSO-M2R5]  78.31 22.67 0 top
SS6  M2.5X3mm  [SMTSO-M2R5]  15.71 22.67 0 top
SW1  SW_PB_ESW  [SW4-4R20X3R25-SM]  3.18 78.48 270 top
SW2  SW_PB_ESW  [SW4-4R20X3R25-SM]  3.18 69.46 270 top
SW3  SW_PB_ESW  [SW4-4R20X3R25-SM]  3.18 60.44 270 top
SW4  SW_PB_ESW  [SW4-4R20X3R25-SM]  3.17 51.44 270 top
U1  MT9700  [SOT23-5]  10.79 32.89 90 bottom
U2  MT9700  [SOT23-5]  18.29 51.18 180 bottom
U3  TP6327GS6  [SOT23_6]  3.3 54.86 90 bottom
U4  TP6327GS6  [SOT23_6]  10.16 54.86 90 bottom
U5  TP6327GS6  [SOT23_6]  3.43 66.04 180 bottom
U6  MT9700  [SOT23-5]  10.79 36.7 90 bottom
U7  MT9700  [SOT23-5]  10.79 40.64 90 bottom
U8  NC  [SOIC8-208]  24.89 35.81 180 bottom
U9  74LVC1G125GW  [SOT-353]  7.75 20.69 90 bottom
U10  74LVC1G125GW  [SOT-353]  7.25 28.45 180 bottom
U11  IRM-V838M3-C/TR1  [SMD4-6R80X2R50]  124.85 11.28 180 top
U12  RX8010SJ  [SOP8]  5.71 74.17 90 bottom
U13  MAX3232CSE  [SOIC16]  35.81 26.29 90 bottom
U14  MAX3485  [SOP8]  65.69 26.06 180 bottom
U15  MAX3485  [SOP8]  51.59 26.06 180 bottom
U16  JL2101-N040C  [QFP_40P_R]  62.87 44.45 0 bottom
U17  TL8821CUB  [RL-UM02WBS-8723BU]  104.2 31.31 180 top
U18  RCLAMP0524P  [USON_10]  91.69 84.83 180 bottom
U19  RCLAMP0524P  [USON_10]  95.25 84.83 180 bottom
U20  RCLAMP0524P  [USON_10]  112.65 83.44 180 bottom
U21  MT9700  [SOT23-5]  121.67 86.61 90 bottom
U22  CH334F  [QFN24]  124.84 82.17 90 top
U24  MT9700  [SOT23-5]  106.05 86.61 90 bottom
U25  MT9700  [SOT23-5]  18.54 67.82 270 bottom
U26  HDMI-001C  [HDMI-SMD]  61.34 76.15 90 top
U27  RCLAMP0524P  [USON_10]  54.46 75.49 90 top
U28  RCLAMP0524P  [USON_10]  54.46 71.98 90 top
U29  MT9700  [SOT23-5]  123.06 62.61 90 top
U30  MT9700  [SOT23-5]  123.06 40.51 90 top
U31  MT9700  [SOT23-5]  123.06 67.44 90 top
U32  MT9700  [SOT23-5]  123.06 45.34 90 top
U33  MT9700  [SOT23-5]  123.06 59.31 90 top
U34  MT9700  [SOT23-5]  123.06 37.21 90 top
U35  MT9700  [SOT23-5]  70.61 26.29 180 bottom
U36  TP6327GS6  [SOT23_6]  101.47 43.43 180 bottom
U37  SIM-7-1  [NANO_SIM]  129.2 40.51 270 bottom
U38  NUP5120X6T1G  [SOT563]  118.87 33.05 180 bottom
Y1  25MHz  [3225]  62.36 35.56 0 bottom
Y2  12MHz  [3225]  124.84 75.44 0 top
Z1  KLXES15AAA1  [ES0402]  2.54 74.55 180 top
Z2  KLXES15AAA1  [ES0402]  6.99 23.49 0 bottom
Z3  KLXES15AAA1  [ES0402]  6.99 24.89 0 bottom
Z4  KLXES15AAA1  [ES0402]  4.57 73.53 180 top
Z5  KLXES15AAA1  [ES0402]  2.16 56.13 90 top
Z7  KLXES15AAA1  [ES0402]  38.73 68.2 0 top
Z8  KLXES15AAA1  [ES0402]  26.29 72.39 0 bottom
Z9  KLXES15AAA1  [ES0402]  28.57 72.39 180 bottom
Z10  KLXES15AAA1  [ES0402]  40.77 68.2 180 top
Z11  KLXES15AAA1  [ES0402]  28.96 68.96 0 bottom
Z13  KLXES15AAA1  [ES0402]  30.99 68.96 180 bottom
Z23  KLXES15AAA1  [ES0402]  2.16 47.37 90 top

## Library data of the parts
C1 C189 C190 = CAP
C2-C43 C47-C76 C79-C113 C116-C131 C136-C145 C150-C157 C162-C178 C181-C188 C191 C192 C431 = CAP_NP
C114 C115 C179 C180 = CAP_NP: signal model: CAP_NP_C0402_DISCRETE_0.1UF_0.1uF
CN1 = WIFI_ANT
D1 D7-D18 D21-D24 D28-D36 D47-D54 Z1-Z5 Z7-Z11 Z13 Z23 = DIODE BI-DIR TRIG
D2 = DIODE
D6 = BAT54C
D19 D20 D27 = DIODE_SCHTKY
D26 = BAT54A
F1 = FUSE
H1-H4 SS1 SS2 SS5 SS6 = SPACER
J1 = DC-044A-20A
J2 = A1501WV-2P
J3 J23 = 1X6PIN
J5 J10 J11 J27 J29 = 1X2PIN
J6 J12 = CON4
J7 = 1.25T-2A
J8 = CON6
J9 = TF_Card
J14 = HY911130A
J15 = USB3D0_USB2D0-A-D
J16 = TYPE-C-31-M-12
J17 = USB-A-D
J18 J19 J22 = FPC-30P
J20 J21 = FPC-24P
J24 = MINI-PCIE
J25 J26 = MIC_JACK
J30 = AS0A826-H2SB-7H
J32 J34-J36 = 1X4PIN
L1-L4 L10 = IND
L5-L9 = BEAD
LED1-LED4 = LED
Q1 Q4 Q5 Q7 Q12 Q13 = MOSFET_P
Q2 Q3 Q6 Q14 = NPN
Q9-Q11 = 2SK3018
R1-R27 R29-R45 R48-R59 R67-R82 R89-R95 R98 R103-R124 R127 R128 R138 R141 R144-R176 R180 R182 R187-R196 R198-R206 R208 R211 R212 R215-R217 R219-R225 R232-R239 = RES
R46 R47 R60-R65 R96 R97 R99-R102 R209 R210 R218 = RES: signal model: RES_R0402_DISCRETE_22R_22R
R66 R177 R179 R183 R185 = RES: signal model: RES_R0402_DISCRETE_0R_0R
R125 R126 R130-R137 R139 R140 R142 R143 R213 R214 = RES: signal model: RES_R0402_DISCRETE_2.2R_2.2R
R178 R181 R184 R186 = RES: signal model: RES_R0402_DISCRETE_NC_NC
SW1-SW4 = SW_PB_ESW
U1 U2 U6 U7 U21 U24 U25 U29-U35 = MT9700
U3-U5 U36 = TP6327GS6
U8 = W25QXX_8P
U9 U10 = 74LVC1G125
U11 = IRM-V838M3-C/TR1
U12 = RX8010SJ
U13 = MAX3232CSE
U14 U15 = TJA1057GT3
U16 = RTL8211F
U17 = RTL8723
U18-U20 U27 U28 = RCLAMP0524P: signal model: RCLAMP0524P_USON_10_RCLAMP0524P_RCLAMP0524P
U22 = CH334F
U26 = HDMI-001C
U37 = SIM-7-1
U38 = NUP5120-D
Y1 Y2 = CRYSTAL_4P

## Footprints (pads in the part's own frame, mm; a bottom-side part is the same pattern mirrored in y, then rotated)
3225
  rect 1.3x1 smd: 1(-1.15,-0.75) 2(1.15,-0.75) 3(1.15,0.75) 4(-1.15,0.75)
AS0A826-H2SB-7H
  round 1.7 hole 1.7 unplated: (-34.3,0)
  round 1.2 hole 1.2 unplated: (34.3,0)
  rect 0.3x2 smd: 1(-33.275,-4.1) 2(-33.025,4.1) 3(-32.775,-4.1) 4(-32.525,4.1) 5(-32.275,-4.1) 6(-32.025,4.1) 7(-31.775,-4.1) 8(-31.525,4.1) 9(-31.275,-4.1) 10(-31.025,4.1) 11(-30.775,-4.1) 12(-30.525,4.1) 13(-30.275,-4.1) 14(-30.025,4.1) 15(-29.775,-4.1) 16(-29.525,4.1) 17(-29.275,-4.1) 18(-29.025,4.1) 19(-28.775,-4.1) 20(-28.525,4.1) 21(-28.275,-4.1) 22(-28.025,4.1) 23(-27.775,-4.1) 24(-27.525,4.1) 25(-27.275,-4.1) 26(-27.025,4.1) 27(-26.775,-4.1) 28(-26.525,4.1) 29(-26.275,-4.1) 30(-26.025,4.1) 31(-25.775,-4.1) 32(-25.525,4.1) 33(-25.275,-4.1) 34(-25.025,4.1) 35(-24.775,-4.1) 36(-24.525,4.1) 37(-24.275,-4.1) 38(-24.025,4.1) 39(-23.775,-4.1) 40(-23.525,4.1) 41(-23.275,-4.1) 42(-23.025,4.1) 43(-22.775,-4.1) 44(-22.525,4.1) 45(-22.275,-4.1) 46(-22.025,4.1) 47(-21.775,-4.1) 48(-21.525,4.1) 49(-21.275,-4.1) 50(-21.025,4.1) 51(-20.775,-4.1) 52(-20.525,4.1) 53(-20.275,-4.1) 54(-20.025,4.1) 55(-19.775,-4.1) 56(-19.525,4.1) 57(-19.275,-4.1) 58(-19.025,4.1) 59(-18.775,-4.1) 60(-18.525,4.1) 61(-18.275,-4.1) 62(-18.025,4.1) 63(-17.775,-4.1) 64(-17.525,4.1) 65(-17.275,-4.1) 66(-17.025,4.1) 67(-16.775,-4.1) 68(-16.525,4.1) 69(-16.275,-4.1) 70(-16.025,4.1) 71(-15.775,-4.1) 72(-15.525,4.1) 73(-15.275,-4.1) 74(-15.025,4.1) 75(-14.775,-4.1) 76(-14.525,4.1) 77(-14.275,-4.1) 78(-14.025,4.1) 79(-13.775,-4.1) 80(-13.525,4.1) 81(-13.275,-4.1) 82(-13.025,4.1) 83(-12.775,-4.1) 84(-12.525,4.1) 85(-12.275,-4.1) 86(-12.025,4.1) 87(-11.775,-4.1) 88(-11.525,4.1) 89(-11.275,-4.1) 90(-11.025,4.1) 91(-10.775,-4.1) 92(-10.525,4.1) 93(-10.275,-4.1) 94(-10.025,4.1) 95(-9.775,-4.1) 96(-9.525,4.1) 97(-9.275,-4.1) 98(-9.025,4.1) 99(-8.775,-4.1) 100(-8.525,4.1) 101(-8.275,-4.1) 102(-8.025,4.1) 103(-7.775,-4.1) 104(-7.525,4.1) 105(-7.275,-4.1) 106(-7.025,4.1) 107(-6.775,-4.1) 108(-6.525,4.1) 109(-6.275,-4.1) 110(-6.025,4.1) 111(-5.775,-4.1) 112(-5.525,4.1) 113(-5.275,-4.1) 114(-5.025,4.1) 115(-4.775,-4.1) 116(-4.525,4.1) 117(-4.275,-4.1) 118(-4.025,4.1) 119(-3.775,-4.1) 120(-3.525,4.1) 121(-3.275,-4.1) 122(-3.025,4.1) 123(-2.775,-4.1) 124(-2.525,4.1) 125(-2.275,-4.1) 126(-2.025,4.1) 127(-1.775,-4.1) 128(-1.525,4.1) 129(-1.275,-4.1) 130(-1.025,4.1) 131(-0.775,-4.1) 132(-0.525,4.1) 133(-0.275,-4.1) 134(-0.025,4.1) 135(0.225,-4.1) 136(0.475,4.1) 137(0.725,-4.1) 138(0.975,4.1) 139(1.225,-4.1) 140(1.475,4.1) 141(1.725,-4.1) 142(1.975,4.1) 143(2.225,-4.1) 144(2.475,4.1) 145(4.725,-4.1) 146(4.975,4.1) 147(5.225,-4.1) 148(5.475,4.1) 149(5.725,-4.1) 150(5.975,4.1) 151(6.225,-4.1) 152(6.475,4.1) 153(6.725,-4.1) 154(6.975,4.1) 155(7.225,-4.1) 156(7.475,4.1) 157(7.725,-4.1) 158(7.975,4.1) 159(8.225,-4.1) 160(8.475,4.1) 161(8.725,-4.1) 162(8.975,4.1) 163(9.225,-4.1) 164(9.475,4.1) 165(9.725,-4.1) 166(9.975,4.1) 167(10.225,-4.1) 168(10.475,4.1) 169(10.725,-4.1) 170(10.975,4.1) 171(11.225,-4.1) 172(11.475,4.1) 173(11.725,-4.1) 174(11.975,4.1) 175(12.225,-4.1) 176(12.475,4.1) 177(12.725,-4.1) 178(12.975,4.1) 179(13.225,-4.1) 180(13.475,4.1) 181(13.725,-4.1) 182(13.975,4.1) 183(14.225,-4.1) 184(14.475,4.1) 185(14.725,-4.1) 186(14.975,4.1) 187(15.225,-4.1) 188(15.475,4.1) 189(15.725,-4.1) 190(15.975,4.1) 191(16.225,-4.1) 192(16.475,4.1) 193(16.725,-4.1) 194(16.975,4.1) 195(17.225,-4.1) 196(17.475,4.1) 197(17.725,-4.1) 198(17.975,4.1) 199(18.225,-4.1) 200(18.475,4.1) 201(18.725,-4.1) 202(18.975,4.1) 203(19.225,-4.1) 204(19.475,4.1) 205(19.725,-4.1) 206(19.975,4.1) 207(20.225,-4.1) 208(20.475,4.1) 209(20.725,-4.1) 210(20.975,4.1) 211(21.225,-4.1) 212(21.475,4.1) 213(21.725,-4.1) 214(21.975,4.1) 215(22.225,-4.1) 216(22.475,4.1) 217(22.725,-4.1) 218(22.975,4.1) 219(23.225,-4.1) 220(23.475,4.1) 221(23.725,-4.1) 222(23.975,4.1) 223(24.225,-4.1) 224(24.475,4.1) 225(24.725,-4.1) 226(24.975,4.1) 227(25.225,-4.1) 228(25.475,4.1) 229(25.725,-4.1) 230(25.975,4.1) 231(26.225,-4.1) 232(26.475,4.1) 233(26.725,-4.1) 234(26.975,4.1) 235(27.225,-4.1) 236(27.475,4.1) 237(27.725,-4.1) 238(27.975,4.1) 239(28.225,-4.1) 240(28.475,4.1) 241(28.725,-4.1) 242(28.975,4.1) 243(29.225,-4.1) 244(29.475,4.1) 245(29.725,-4.1) 246(29.975,4.1) 247(30.225,-4.1) 248(30.475,4.1) 249(30.725,-4.1) 250(30.975,4.1) 251(31.225,-4.1) 252(31.475,4.1) 253(31.725,-4.1) 254(31.975,4.1) 255(32.225,-4.1) 256(32.475,4.1) 257(32.725,-4.1) 258(32.975,4.1) 259(33.225,-4.1) 260(33.475,4.1)
  rect 4.5x4.6 smd: 261(-33.7,12) 262(33.9,12)
C0402
  rect 0.599x0.599 smd: 1(-0.5,0) 2(0.5,0)
C0603
  rect 0.8x0.8 smd: 1(-0.8,0) 2(0.8,0)
DB2ERC-3P81-4P
  rect 1.8x1.8 hole 1.2: 1(-5.715,0)
  round 1.8 hole 1.2: 2(-1.905,0) 3(1.905,0) 4(5.715,0)
DB2ERC-3P81-6P
  rect 1.8x1.8 hole 1.2: 1(-9.525,0)
  round 1.8 hole 1.2: 2(-5.715,0) 3(-1.905,0) 4(1.905,0) 5(5.715,0) 6(9.525,0)
DC_IN_TH_3P_10R1X11R6
  round 1.999 hole 1.999 unplated: (-1.699,-1.25)
  oval 2.4x1.001 hole 1.801x0.399: 1(-2.751,-4.9) 5(-2.751,4.9)
  oval 2.601x1.1 hole 1.699x0.5: 2(4.501,-1.25) 3(4.501,4.049) 4(4.501,-4.45)
EAR_JACK
  oval 1.4x2.6 hole 1x2: 1(-6.1,-0.9) 2(-3.7,1.1) 3(1.8,1.1) 4(5.9,-0.9) 5(0,-0.9)
EC6P3
  rect 1.001x1.999 smd: 1(0,2.8) 2(0,-2.8)
ES0402
  rect 0.599x0.599 smd: 1(-0.5,0) 2(0.5,0)
F1812
  rect 1.78x3.3 smd: 1(-2.305,0) 2(2.305,0)
FPC-30P-0P5
  rect 0.3x1.3 smd: 1(-7.25,1.35) 2(-6.75,1.35) 3(-6.25,1.35) 4(-5.75,1.35) 5(-5.25,1.35) 6(-4.75,1.35) 7(-4.25,1.35) 8(-3.75,1.35) 9(-3.25,1.35) 10(-2.75,1.35) 11(-2.25,1.35) 12(-1.75,1.35) 13(-1.25,1.35) 14(-0.75,1.35) 15(-0.25,1.35) 16(0.25,1.35) 17(0.75,1.35) 18(1.25,1.35) 19(1.75,1.35) 20(2.25,1.35) 21(2.75,1.35) 22(3.25,1.35) 23(3.75,1.35) 24(4.25,1.35) 25(4.75,1.35) 26(5.25,1.35) 27(5.75,1.35) 28(6.25,1.35) 29(6.75,1.35) 30(7.25,1.35)
  rect 1.6x2 smd: 31(9.4,-1.35) 32(-9.4,-1.35)
FPC_24P_0P5
  rect 0.3x1.3 smd: 1(-5.75,-1.351) 2(-5.25,-1.351) 3(-4.75,-1.351) 4(-4.25,-1.351) 5(-3.75,-1.351) 6(-3.25,-1.351) 7(-2.75,-1.351) 8(-2.25,-1.351) 9(-1.75,-1.351) 10(-1.25,-1.351) 11(-0.75,-1.351) 12(-0.25,-1.351) 13(0.25,-1.351) 14(0.75,-1.351) 15(1.25,-1.351) 16(1.75,-1.351) 17(2.25,-1.351) 18(2.75,-1.351) 19(3.25,-1.351) 20(3.75,-1.351) 21(4.25,-1.351) 22(4.75,-1.351) 23(5.25,-1.351) 24(5.75,-1.351)
  rect 1.6x2 smd: 25(7.45,1.351) 26(-7.45,1.351)
GH1P25_TH_2P
  rect 0.9x0.9 hole 0.5: 1(-0.625,0)
  round 0.9 hole 0.5: 2(0.625,0)
HDMI-SMD
  round 1.999 hole 1.999 unplated: (-6.05,-2) (7.2,1.5)
  round 0.8 hole 0.55: 1(5.3,0.5) 2(4.731,-0.5) 3(4.145,0.5) 4(3.575,-0.5) 5(2.99,0.5) 6(2.419,-0.5) 7(1.835,0.5) 8(1.263,-0.5) 9(0.68,0.5) 10(0.107,-0.5) 11(-0.475,0.5) 12(-1.049,-0.5) 13(-1.63,0.5) 14(-2.205,-0.5) 15(-2.785,0.5) 16(-3.361,-0.5) 17(-3.94,0.5) 18(-4.517,-0.5) 19(-5.095,0.5)
  oval 3.2x1.4 hole 2.7x0.9: G1(-6.05,3.25) G2(3.45,3.25) G3(-2.95,-3.25) G4(6.05,-3.25)
HDR1X2-2R54-TM-VM
  rect 1.6x1.6 hole 1: 1(-1.27,0)
  round 1.6 hole 1: 2(1.27,0)
HY911130A
  round 3.25 hole 3.25 unplated: (-5.715,0) (5.715,0)
  round 1.6 hole 1: 1(5.72,-8.89) 2(4.45,-6.35) 3(3.18,-8.89) 4(1.91,-6.35) 5(0.64,-8.89) 6(-0.63,-6.35) 7(-1.9,-8.89) 8(-3.17,-6.35) 9(-4.44,-8.89) 10(-5.71,-6.35)
  round 1.8 hole 1.2: 11(6.625,4.9) 12(4.085,4.9) 13(-4.085,4.9) 14(-6.625,4.9)
  round 2.43 hole 1.83: 15(7.745,-3.05) 16(-7.745,-3.05)
L0603
  rect 0.8x0.8 smd: 1(-0.8,0) 2(0.8,0)
L2520
  rect 1.118x2.032 smd: 1(-0.959,0) 2(0.959,0)
L4520
  rect 1.4x2.3 smd: 1(-1.8,0) 2(1.8,0)
LED0603
  rect 0.93x0.98 smd: 1(0.77,0) 2(-0.77,0)
NANO_SIM
  round 0.9 hole 0.9 unplated: (-5,-5.49) (3.5,-5.49)
  rect 0.5x1.3 smd: 1(0.25,6.74) 2(-2.29,6.74) 3(-4.83,6.74) 4(2.47,6.74) 5(1.52,6.74) 6(-1.02,6.74) 7(-3.56,6.74)
  rect 1x2.1 smd: 8(-6.5,5.26) 9(6.5,5.26) 10(-6.5,-6.74) 11(6.5,-6.74)
NPTH_M3
  round 3.2 hole 3.2 unplated: (0,0)
PCIE_52P
  round 1.6 hole 1.6 unplated: (-12.5,0)
  round 1.1 hole 1.1 unplated: (12.5,0)
  rect 0.6x2 smd: 1(-11.8,-4.1) 2(-11.4,4.1) 3(-11,-4.1) 4(-10.6,4.1) 5(-10.2,-4.1) 6(-9.8,4.1) 7(-9.4,-4.1) 8(-9,4.1) 9(-8.6,-4.1) 10(-8.2,4.1) 11(-7.8,-4.1) 12(-7.4,4.1) 13(-7,-4.1) 14(-6.6,4.1) 15(-6.2,-4.1) 16(-5.8,4.1) 17(-2.2,-4.1) 18(-1.8,4.1) 19(-1.4,-4.1) 20(-1,4.1) 21(-0.6,-4.1) 22(-0.2,4.1) 23(0.2,-4.1) 24(0.6,4.1) 25(1,-4.1) 26(1.4,4.1) 27(1.8,-4.1) 28(2.2,4.1) 29(2.6,-4.1) 30(3,4.1) 31(3.4,-4.1) 32(3.8,4.1) 33(4.2,-4.1) 34(4.6,4.1) 35(5,-4.1) 36(5.4,4.1) 37(5.8,-4.1) 38(6.2,4.1) 39(6.6,-4.1) 40(7,4.1) 41(7.4,-4.1) 42(7.8,4.1) 43(8.2,-4.1) 44(8.6,4.1) 45(9,-4.1) 46(9.4,4.1) 47(9.8,-4.1) 48(10.2,4.1) 49(10.6,-4.1) 50(11,4.1) 51(11.4,-4.1) 52(11.8,4.1)
  rect 2.15x2.6 smd: 53(14.65,-3.5) 54(-14.65,-3.5)
PH-1X2-2P0_L
  rect 1.1x1.1 hole 0.7: 1(-1,0)
  round 1.1 hole 0.7: 2(1,0)
PH-1X4-2P0
  rect 1.1x1.1 hole 0.7: 1(-3,0)
  round 1.1 hole 0.7: 2(-1,0) 3(1,0) 4(3,0)
PH-1X6-2P0
  rect 1.1x1.1 hole 0.7: 1(-5,0)
  round 1.1 hole 0.7: 2(-3,0) 3(-1,0) 4(1,0) 5(3,0) 6(5,0)
QFN24
  rect 1x0.3 smd: 1(-2.1,1.25) 2(-2.1,0.75) 3(-2.1,0.25) 4(-2.1,-0.25) 5(-2.1,-0.75) 6(-2.1,-1.25) 13(2.1,-1.25) 14(2.1,-0.75) 15(2.1,-0.25) 16(2.1,0.25) 17(2.1,0.75) 18(2.1,1.25)
  rect 0.3x1 smd: 7(-1.25,-2.1) 8(-0.75,-2.1) 9(-0.25,-2.1) 10(0.25,-2.1) 11(0.75,-2.1) 12(1.25,-2.1) 19(1.25,2.1) 20(0.75,2.1) 21(0.25,2.1) 22(-0.25,2.1) 23(-0.75,2.1) 24(-1.25,2.1)
  rect 2x2 smd: 25(0,0)
QFP_40P_R
  oval 0.8x0.22 smd: 1(-2.5,1.8) 2(-2.5,1.4) 3(-2.5,1) 4(-2.5,0.6) 5(-2.5,0.2) 6(-2.5,-0.2) 7(-2.5,-0.6) 8(-2.5,-1) 9(-2.5,-1.4) 10(-2.5,-1.8) 21(2.5,-1.8) 22(2.5,-1.4) 23(2.5,-1) 24(2.5,-0.6) 25(2.5,-0.2) 26(2.5,0.2) 27(2.5,0.6) 28(2.5,1) 29(2.5,1.4) 30(2.5,1.8)
  oval 0.22x0.8 smd: 11(-1.8,-2.5) 12(-1.4,-2.5) 13(-1,-2.5) 14(-0.6,-2.5) 15(-0.2,-2.5) 16(0.2,-2.5) 17(0.6,-2.5) 18(1,-2.5) 19(1.4,-2.5) 20(1.8,-2.5) 31(1.8,2.5) 32(1.4,2.5) 33(1,2.5) 34(0.6,2.5) 35(0.2,2.5) 36(-0.2,2.5) 37(-0.6,2.5) 38(-1,2.5) 39(-1.4,2.5) 40(-1.8,2.5)
  rect 3x3 smd: 41(0,0)
R0402
  rect 0.599x0.599 smd: 1(-0.5,0) 2(0.5,0)
R0603
  rect 0.8x0.8 smd: 1(-0.8,0) 2(0.8,0)
RL-UM02WBS-8723BU
  oval 2x1 smd: 1(-6.3,3.97) 2(-6.3,1.97) 3(-6.3,-1.01) 4(-6.3,-3.17) 5(6.3,3.5) 6(6.3,0.97) 7(6.3,-2.53) 8(6.3,-5.33)
  oval 1x2 smd: 9(3.65,-6.9) 10(2.38,-6.9) 11(1.11,-6.9) 12(-0.16,-6.9) 13(-1.43,-6.9) 14(-2.7,-6.9)
SMA214-CA
  rect 2.1x1.8 smd: 1(-2.2,0) 2(2.2,0)
SMB-CA
  rect 2.4x2.8 smd: 1(-2.3,0) 2(2.3,0)
SMD4-6R80X2R50
  rect 0.8x1.2 smd: 1(1.905,0) 2(0.635,0) 3(-0.635,0) 4(-1.905,0)
SMTSO-M2R5
  round 6.2 hole 4.22: 1(0,0)
SOD523
  rect 0.6x0.7 smd: 1(-0.71,0) 2(0.71,0)
SOD-123
  rect 1.2x1.4 smd: 1(1.7,0) 2(-1.7,0)
SOIC8-208
  rect 1.778x0.635 smd: 1(-4,1.905) 2(-4,0.635) 3(-4,-0.635) 4(-4,-1.905) 5(4,-1.905) 6(4,-0.635) 7(4,0.635) 8(4,1.905)
SOIC16
  oval 2.032x0.61 smd: 1(-2.789,4.44) 2(-2.789,3.18) 3(-2.789,1.9) 4(-2.789,0.64) 5(-2.789,-0.64) 6(-2.789,-1.9) 7(-2.789,-3.18) 8(-2.789,-4.44) 9(2.789,-4.44) 10(2.789,-3.18) 11(2.789,-1.9) 12(2.789,-0.64) 13(2.789,0.64) 14(2.789,1.9) 15(2.789,3.18) 16(2.789,4.44)
SOP8
  oval 0.6x1.8 smd: 1(-1.905,-2.5) 2(-0.635,-2.5) 3(0.635,-2.5) 4(1.905,-2.5) 5(1.905,2.5) 6(0.635,2.5) 7(-0.635,2.5) 8(-1.905,2.5)
SOT23
  rect 0.914x0.914 smd: 1(-0.953,-0.991) 2(0.953,-0.991)
  rect 0.914x1.27 smd: 3(0,1.041)
SOT23-5
  rect 0.599x1.199 smd: 1(-0.95,-1.25) 2(0,-1.25) 3(0.95,-1.25) 4(0.95,1.25) 5(-0.95,1.25)
SOT23_6
  rect 0.7x0.9 smd: 1(-0.95,-1.2) 2(0,-1.2) 3(0.95,-1.2) 4(0.95,1.2) 5(0,1.2) 6(-0.95,1.2)
SOT563
  rect 0.3x0.45 smd: 1(-0.5,-0.675) 2(0,-0.675) 3(0.5,-0.675) 4(0.5,0.675) 5(0,0.675) 6(-0.5,0.675)
SOT-353
  rect 0.406x1.194 smd: 1(-0.65,-0.9) 2(0,-0.9) 3(0.65,-0.9) 4(0.65,0.9) 5(-0.65,0.9)
SW4-4R20X3R25-SM
  rect 1.2x0.65 smd: 1(-2.15,1.075) 2(2.15,1.075) 3(2.15,-1.075) 4(-2.15,-1.075)
T3R2-5R2_TOPSMT
  round 5.2 hole 3.2: 1(0,0)
TFCARD
  round 1.016 hole 1.016 unplated: (-4,0) (4,0)
  rect 0.7x1.6 smd: 1(3.2,10.5) 2(2.1,10.5) 3(1,10.5) 4(-0.1,10.5) 5(-1.2,10.5) 6(-2.3,10.5) 7(-3.4,10.5) 8(-4.5,10.5) 9(-5.6,10.5)
  rect 1.2x1.778 smd: 10(-6.8,10)
  rect 1.524x2.413 smd: 11(-6.8,0.4) 12(8.7,0.4)
  rect 1.778x1.778 smd: 13(7.8,10)
TYPE-C-31-M-12
  round 0.65 hole 0.65 unplated: (-2.891,-1.44) (2.891,-1.44)
  rect 0.3x2 smd: A1(-3.35,0.279) A4(-2.55,0.279) A5(-1.25,0.279) A6(-0.249,0.279) A7(0.249,0.279) A8(1.25,0.279) A9(2.55,0.279) A12(3.35,0.279) B1(3.051,0.279) B4(2.25,0.279) B5(1.75,0.279) B6(0.749,0.279) B7(-0.749,0.279) B8(-1.75,0.279) B9(-2.25,0.279) B12(-3.051,0.279)
  oval 1.1x1.7 hole 0.6x1.2: C1(-4.321,-5.1) C2(4.321,-5.1)
  oval 1.1x2.2 hole 0.6x1.7: C3(-4.321,-0.909) C4(4.321,-0.909)
UFL-3
  rect 1.05x1.05 smd: 1(0,-1.5)
  rect 1.05x2.2 smd: 2(-1.5,0) 3(1.5,0)
unnamed#2
  round 1.016 smd: 1(0,0)
USB3D0-AF-18P
  round 1.1 hole 0.7: 1(-3.5,-1.5) 2(-1,-1.5) 3(1,-1.5) 4(3.5,-1.5) 5(4,0) 6(2,0) 7(0,0) 8(-2,0) 9(-4,0) 10(-3.5,1.7) 11(-1,1.7) 12(1,1.7) 13(3.5,1.7) 14(4,3.2) 15(2,3.2) 16(0,3.2) 17(-2,3.2) 18(-4,3.2)
  round 3.2 hole 2.4: 19(6.57,-3.5) 20(6.57,2.18) 21(-6.57,2.18) 22(-6.57,-3.5)
USB-A-D
  round 1.6 hole 1: 1(3.5,-6.5) 2(1,-6.5) 3(-1,-6.5) 4(-3.5,-6.5) 7(3.5,-3.5) 8(1,-3.5) 9(-1,-3.5) 10(-3.5,-3.5)
  round 2.6 hole 2: 5(-6.55,-6.5) 6(6.55,-6.5) 11(-6.55,-0.7) 12(6.55,-0.7)
USON_10
  rect 0.3x0.55 smd: 1(-1,-0.4) 2(-0.5,-0.4) 4(0.5,-0.4) 5(1,-0.4) 6(1,0.4) 7(0.5,0.4) 9(-0.5,0.4) 10(-1,0.4)
  rect 0.4x0.55 smd: 3(0,-0.4) 8(0,0.4)
XH2P54-4P
  rect 1.45x1.45 hole 0.85: 1(-3.81,0)
  round 1.45 hole 0.85: 2(-1.27,0) 3(1.27,0) 4(3.81,0)
ZH1P5MM_TH_2P
  round 1.05 hole 0.65: 1(-0.75,0) 2(0.75,0)

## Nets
1V05_AVDD_PHY: C99.1 C100.1 C101.1 C102.1 R124.2 U16.3(AVDD10_2) U16.8(AVDD10_1) U16.38(AVDD10)
1V05_DVDD_PHY: C95.1 C96.1 C97.1 C98.1 R123.1 U16.21(DVDD10)
1V05_PHY: C81.1 C82.1 L4.2 R123.2 R124.1
1V8_DVDD_PHY: C103.1 C104.1 L7.1 R89.2 R90.1 R106.1 R119.1
3V3_AVDD_PHY: C91.1 C92.1 C93.1 L6.1 U16.11(AVDD33_1) U16.40(AVDD33)
3V3_DVDD_PHY: C87.1 C88.1 C89.1 L5.1 R91.2 R92.2 R107.2 R110.1 R118.2 R120.1 R122.2 U16.29(DVDD33)
3V3_EDP: C163.1 C164.1 J22.12 J22.13 J23.1 R189.1 R190.1 R191.1 U35.1(OUT)
3V3_IMAGE_1: C142.1 C143.1 J18.4 J18.5 R163.1 R167.1 U31.1(OUT)
3V3_IMAGE_2: C144.1 C145.1 J19.4 J19.5 R165.1 R169.1 U32.1(OUT)
3V3_OUT: C42.1 C43.1 J3.5 U6.1(OUT)
3V3_WLAN: C110.1 C111.1 Q7.3(DRAIN) U17.8(VCC3V3)
5V0_CAM_1: C151.1 C152.1 J20.1 J20.2 J20.3 U33.1(OUT)
5V0_CAM_2: C154.1 C155.1 J21.1 J21.2 J21.3 U34.1(OUT)
5V0_IMAGE_1: C140.1 C141.1 J18.1 J18.2 J18.3 U29.1(OUT)
5V0_IMAGE_2: C137.1 C138.1 J19.1 J19.2 J19.3 U30.1(OUT)
5V_OUT: C48.1 C49.1 J3.3 U7.1(OUT)
12V_EDP: C166.1 C167.1 J22.26 J22.27 J22.28 J22.29 Q13.3(DRAIN)
12V_OUT: C39.1 C40.1 J3.1 Q5.3(DRAIN)
GND: C1.2 C2.2 C3.2 C4.2 C5.2 C6.2 C9.2 C10.2 C11.2 C12.2 C13.2 C14.2 C15.2 C16.2 C17.2 C18.1 C21.2 C22.2 C23.2 C24.2 C25.2 C26.2 C27.1 C30.2 C31.2 C32.2 C33.2 C34.2 C35.2 C36.2 C37.1 C39.2 C40.2 C41.2 C42.2 C43.2 C47.2 C48.2 C49.2 C50.2 C51.2 C52.2 C53.2 C54.2 C55.2 C56.2 C57.2 C58.2 C59.2 C60.2 C61.2 C62.2 C63.2 C64.2 C65.2 C66.2 C67.2 C68.2 C69.2 C70.2 C73.2 C74.2 C75.2 C76.2 C79.2 C80.2 C81.2 C82.2 C83.2 C84.2 C85.2 C86.2 C87.2 C88.2 C89.2 C90.2 C91.2 C92.2 C93.2 C94.2 C95.2 C96.2 C97.2 C98.2 C99.2 C100.2 C101.2 C102.2 C103.2 C104.2 C105.2 C107.2 C108.2 C110.2 C111.2 C112.2 C113.2 C116.2 C117.2 C118.2 C119.2 C120.1 C121.2 C122.2 C123.2 C124.2 C125.2 C126.2 C127.2 C128.2 C129.2 C130.2 C131.2 C136.2 C137.2 C138.2 C139.2 C140.2 C141.2 C142.2 C143.2 C144.2 C145.2 C150.2 C151.2 C152.2 C153.2 C154.2 C155.2 C162.2 C163.2 C164.2 C166.2 C167.2 C170.2 C171.2 C172.2 C173.2 C174.2 C175.2 C176.2 C177.2 C178.2 C181.2 C182.2 C183.2 C184.2 C185.2 C186.2 C187.2 C191.2 C192.2 C431.2 CN1.2 CN1.3 D1.1 D2.2(A) D7.1 D8.1 D9.1 D10.1 D11.1 D12.1 D13.1 D14.1 D15.1 D16.1 D17.1 D18.1 D21.1 D22.1 D23.1 D24.1 D28.1 D29.1 D30.1 D31.1 D32.1 D33.1 D34.1 D35.1 D36.1 D47.1 D48.1 D49.1 D50.1 D51.1 D52.1 D53.1 D54.1 J1.1 J1.2 J1.3 J1.5 J2.2 J3.2 J3.4 J3.6 J5.1 J6.4 J7.2 J8.2 J8.5 J9.6(VSS) J9.10(GND10) J9.11(GND11) J9.12(GND12) J9.13(GND13) J14.10(CHS) J14.15(SH) J14.16(SH1) J15.4(GND1) J15.7(GND2) J15.13(GND1) J15.16(NC3) J15.19(SH1) J15.20(SH2) J15.21(SH1) J15.22(SH2) J16.A1(GND1) J16.A12(GND2) J16.B1(GND4) J16.B12(GND3) J17.4(GND) J17.5(SH1) J17.6(SH2) J17.10(GND) J17.11(SH1) J17.12(SH2) J18.6 J18.7 J18.8 J18.16 J18.19 J18.22 J18.25 J18.28 J18.31(SH1) J18.32(SH2) J19.6 J19.7 J19.8 J19.16 J19.19 J19.22 J19.25 J19.28 J19.31(SH1) J19.32(SH2) J20.4 J20.18 J20.21 J20.23 J20.24 J20.25(SH1) J20.26(SH2) J21.4 J21.23 J21.24 J21.25(SH1) J21.26(SH2) J22.2 J22.5 J22.8 J22.11 J22.15 J22.16 J22.18 J22.19 J22.20 J22.21 J22.31(SH1) J22.32(SH2) J23.6 J24.4(GND9) J24.9(GND1) J24.15(GND2) J24.18(GND10) J24.21(GND3) J24.26(GND11) J24.27(GND4) J24.29(GND5) J24.34(GND12) J24.35(GND6) J24.37(GND7) J24.40(GND13) J24.43(GND8) J24.50(GND14) J24.53 J24.54 J30.1(P1) J30.2(P2) J30.15(P15) J30.38(P38) J30.53(P53) J30.56(P56) J30.60(P60) J30.63(P63) J30.74(P74) J30.77(P77) J30.80(P80) J30.94(P94) J30.102(P102) J30.103(P103) J30.124(P124) J30.125(P125) J30.134(P134) J30.143(P143) J30.144(P144) J30.145(P145) J30.146(P146) J30.157(P157) J30.164(P164) J30.169(P169) J30.179(P179) J30.180(P180) J30.193(P193) J30.198(P198) J30.206(P206) J30.207(P207) J30.220(P220) J30.228(P228) J30.229(P229) J30.234(P234) J30.237(P237) J30.249(P249) J30.250(P250) J30.251(P251) J30.252(P252) J30.253(P253) J30.254(P254) J30.261(SHIELD_1) J30.262(SHIELD_2) J32.4 J34.4 J35.4 J36.4 L8.2 L9.2 Q2.2(EMITTER) Q3.2(EMITTER) Q6.2(EMITTER) Q14.2(EMITTER) R2.2 R5.2 R6.2 R8.2 R13.2 R15.2 R18.2 R21.2 R22.2 R25.2 R30.2 R32.2 R34.2 R36.2 R75.2 R76.2 R77.2 R78.2 R98.2 R103.2 R104.2 R105.2 R111.2 R114.2 R115.2 R116.2 R121.1 R144.2 R148.2 R151.2 R153.2 R155.2 R173.2 R174.2 R175.2 R176.2 R182.2 R188.2 R192.1 R195.2 R199.2 R205.2 R219.2 R220.2 R221.2 SS1.1(NC_1) SS2.1(NC_1) SS5.1(NC_1) SS6.1(NC_1) SW1.1(A1) SW1.2(A2) SW2.1(A1) SW2.2(A2) SW3.1(A1) SW3.2(A2) SW4.1(A1) SW4.2(A2) U1.2(GND) U2.2(GND) U3.1(GND) U4.1(GND) U5.1(GND) U6.2(GND) U7.2(GND) U8.4(GND) U9.1(\\O\E) U9.3(GND) U10.1(\\O\E) U10.3(GND) U11.1(GND1) U11.4(GND2) U12.4(GND) U13.15(GND) U14.5(GND) U15.5(GND) U16.41(GND) U17.1(GND#1) U17.5(GND#5) U18.3(GND1) U18.8(GND2) U19.3(GND1) U19.8(GND2) U20.3(GND1) U20.8(GND2) U21.2(GND) U22.25(VSS) U24.2(GND) U25.2(GND) U26.2 U26.5 U26.8 U26.11 U26.17 U27.3(GND1) U27.8(GND2) U28.3(GND1) U28.8(GND2) U29.2(GND) U30.2(GND) U31.2(GND) U32.2(GND) U33.2(GND) U34.2(GND) U35.2(GND) U36.1(GND) U37.5(GND) U37.8(SH1) U37.9(SH2) U37.10(SH3) U37.11(SH4) U38.2 Y1.2(GND1) Y1.4(GND2) Y2.2(GND1) Y2.4(GND2) Z1.1 Z2.2 Z3.2 Z4.1 Z5.1 Z7.1 Z8.1 Z9.1 Z10.1 Z11.1 Z13.1 Z23.1
VCC3V3_SD: C54.1 C73.1 C74.1 J9.4(VDD) J30.243(P243) J30.244(P244)
VCC3V3_SYS: C8.1 C15.1 C16.1 C17.1 L1.2 R4.1 U1.5(IN) U6.5(IN) U31.5(IN) U32.5(IN) U35.5(IN)
VCC5V0_SYS: C20.1 C24.1 C25.1 C26.1 C50.1 C51.1 J30.255(P255) J30.256(P256) J30.257(P257) J30.258(P258) J30.259(P259) J30.260(P260) L2.2 R11.1 R16.1 U2.5(IN) U29.5(IN) U30.5(IN) U33.5(IN) U34.5(IN)
VCC5V0_SYS_2: C29.1 C34.1 C35.1 C36.1 L3.2 R10.1 R20.1 U7.5(IN) U21.5(IN) U24.5(IN) U25.5(IN)
VCC5V0_USB20_HOST: C112.1 C113.1 C116.1 C117.1 J17.1(VBUS) J17.7(VBUS) U21.1(OUT)
